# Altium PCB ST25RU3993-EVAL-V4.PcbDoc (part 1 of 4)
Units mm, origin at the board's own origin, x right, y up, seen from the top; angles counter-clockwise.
Board outline 76.25 x 96.25 mm, 6 copper layers (Top Layer, RF GND, Power, GND, Routing, Bottom GND), stack 1.022 mm thick; 319 components, 214 nets, 994 pads, 1429 vias.
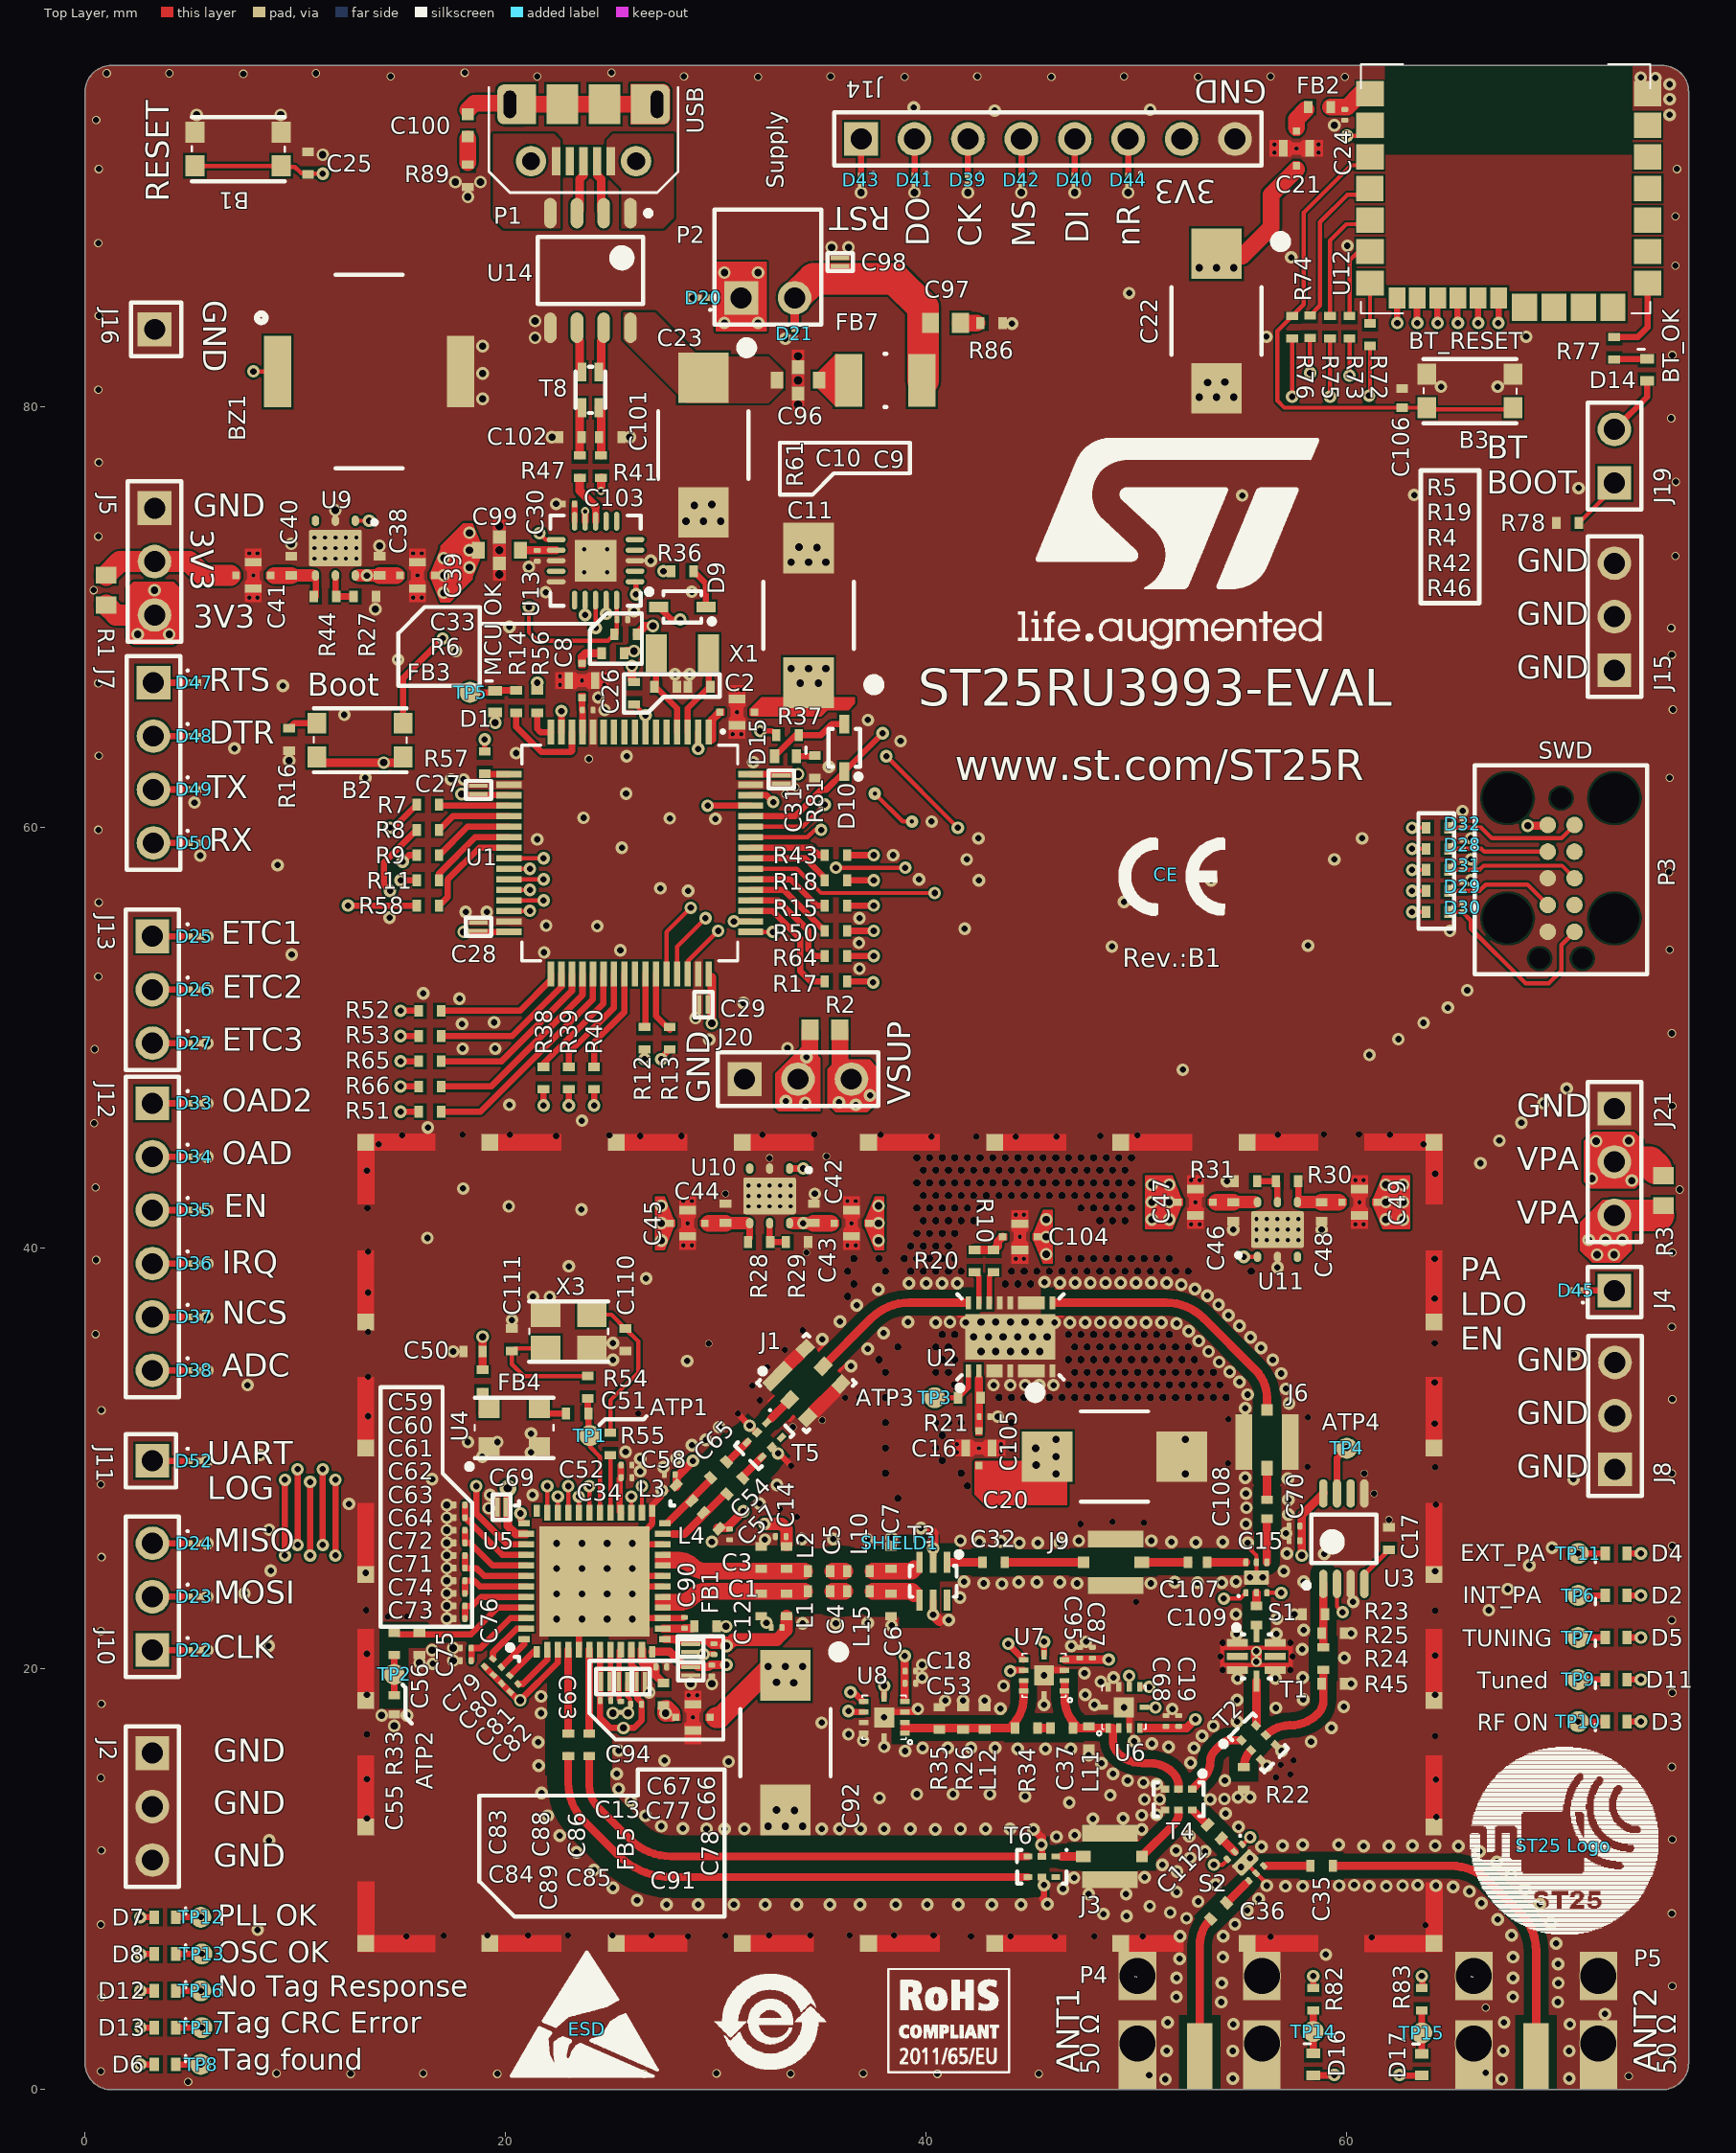
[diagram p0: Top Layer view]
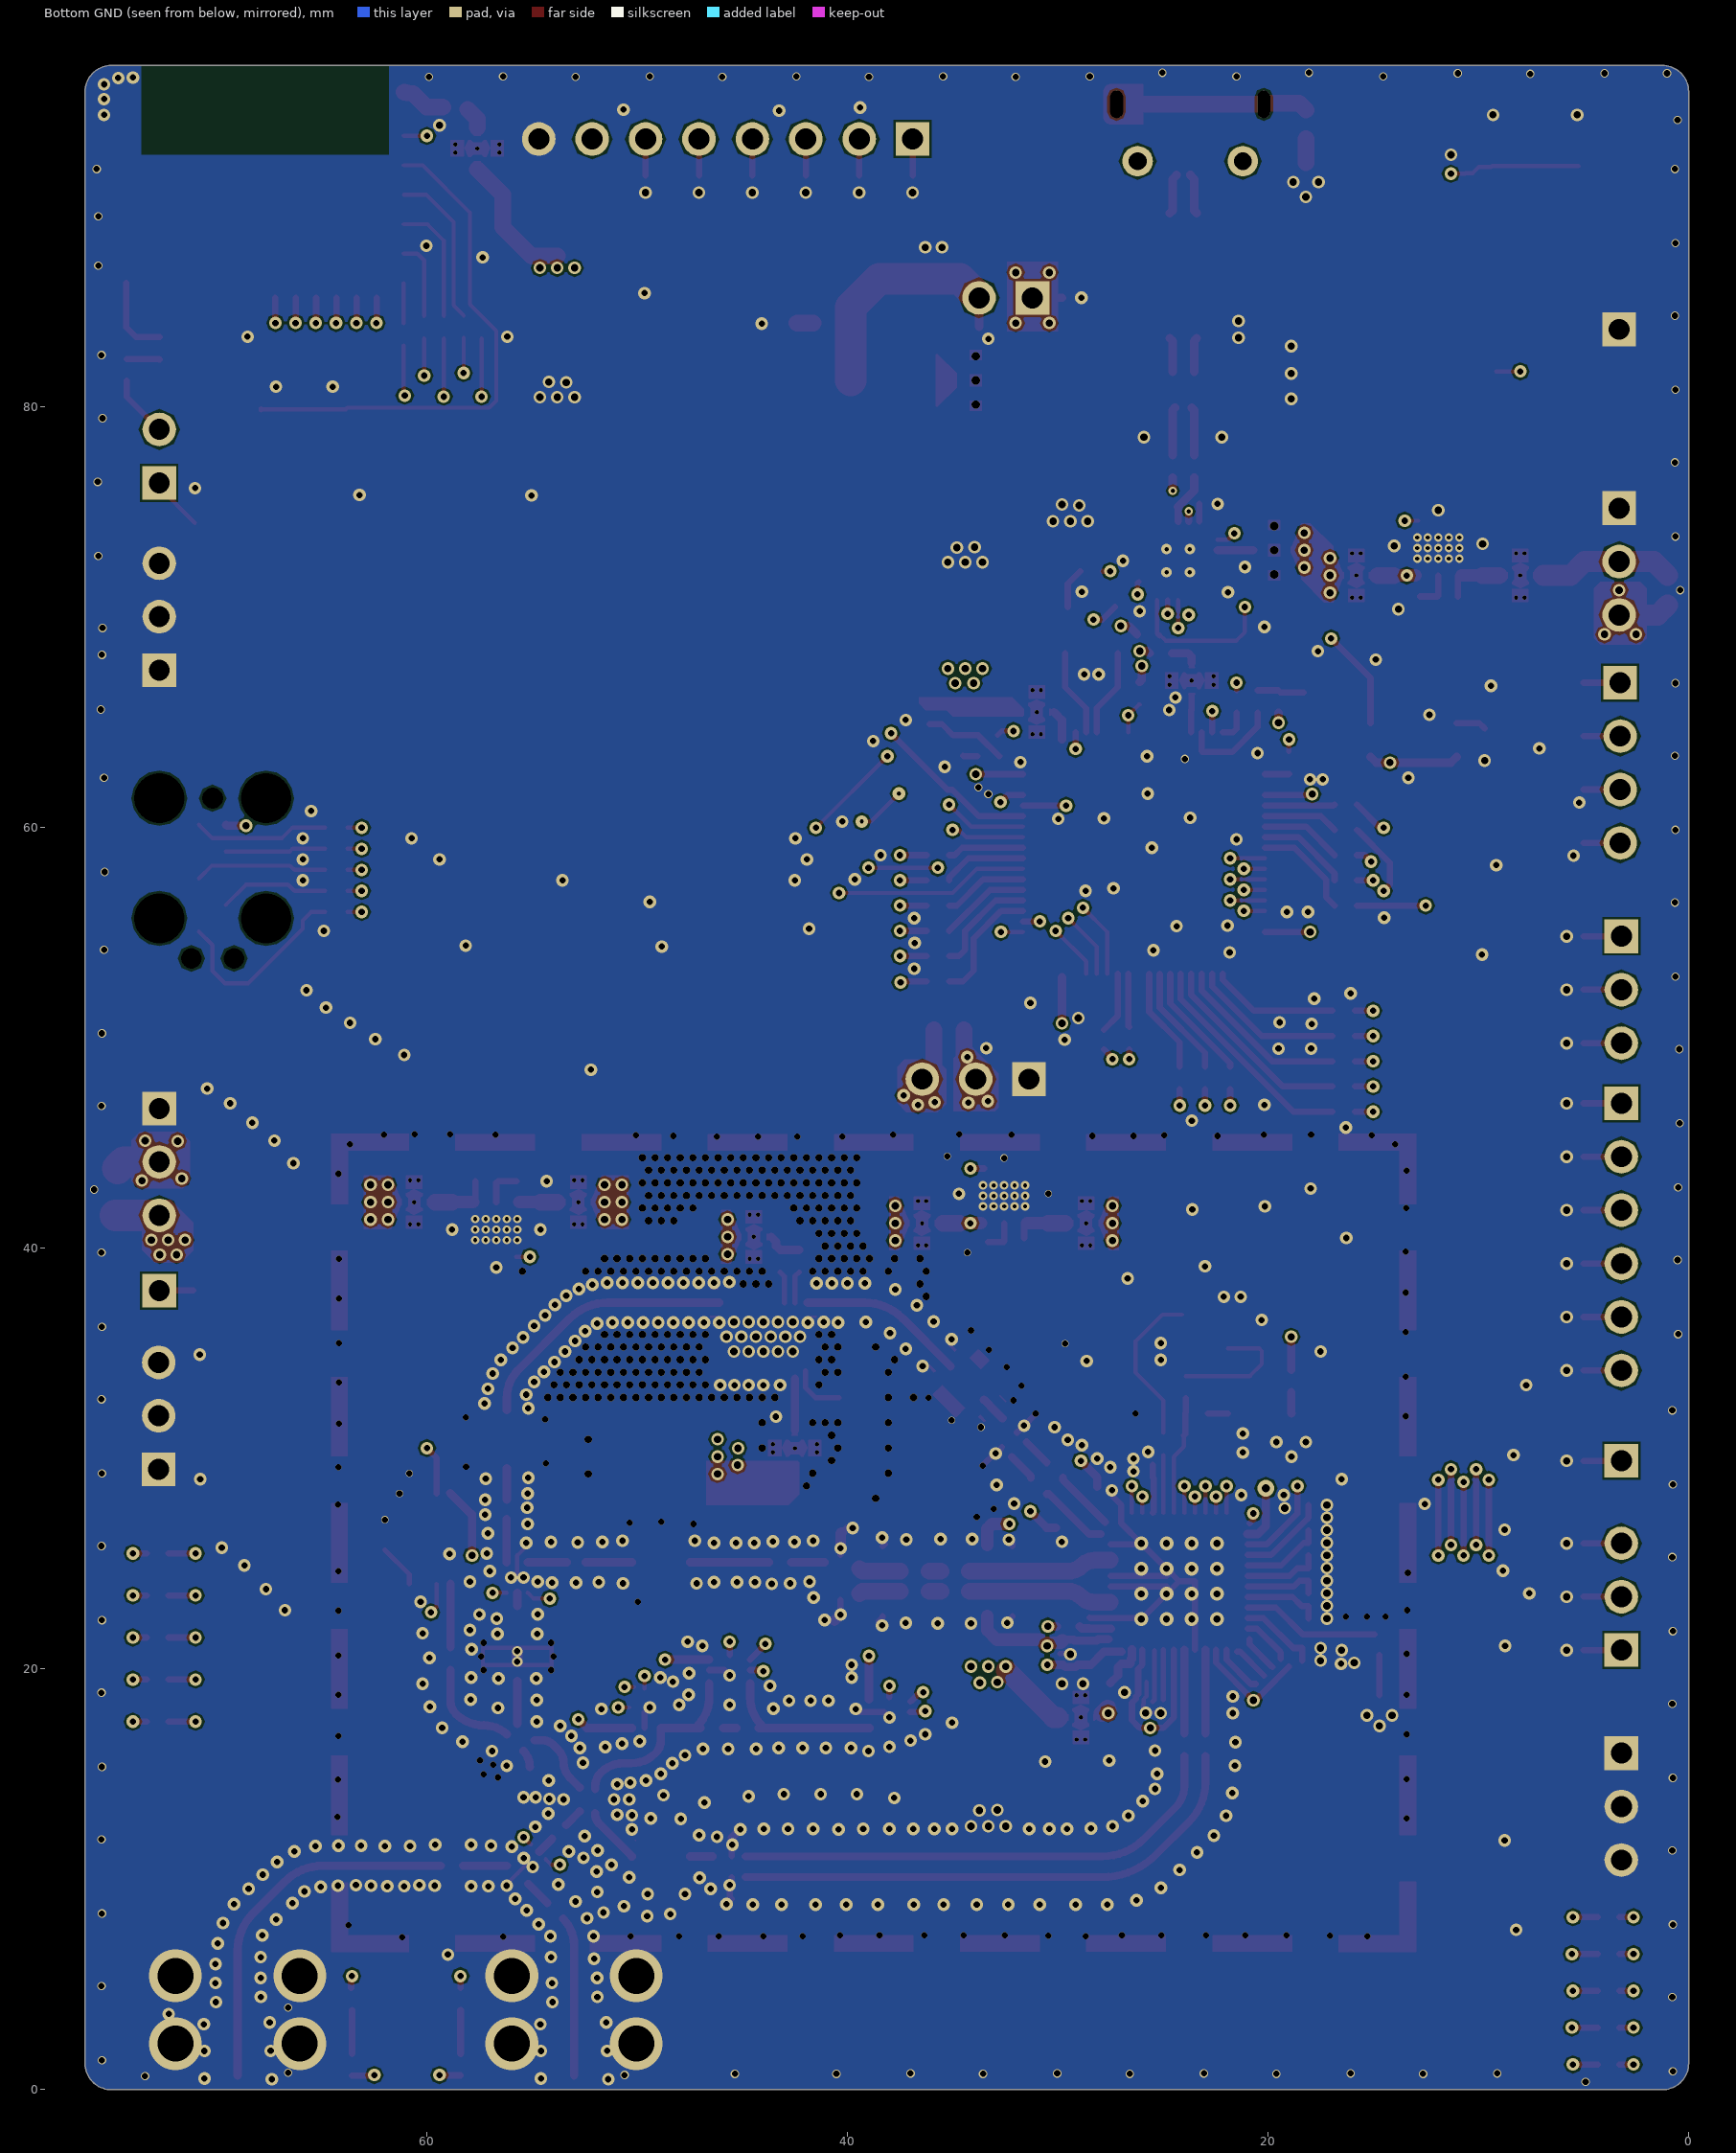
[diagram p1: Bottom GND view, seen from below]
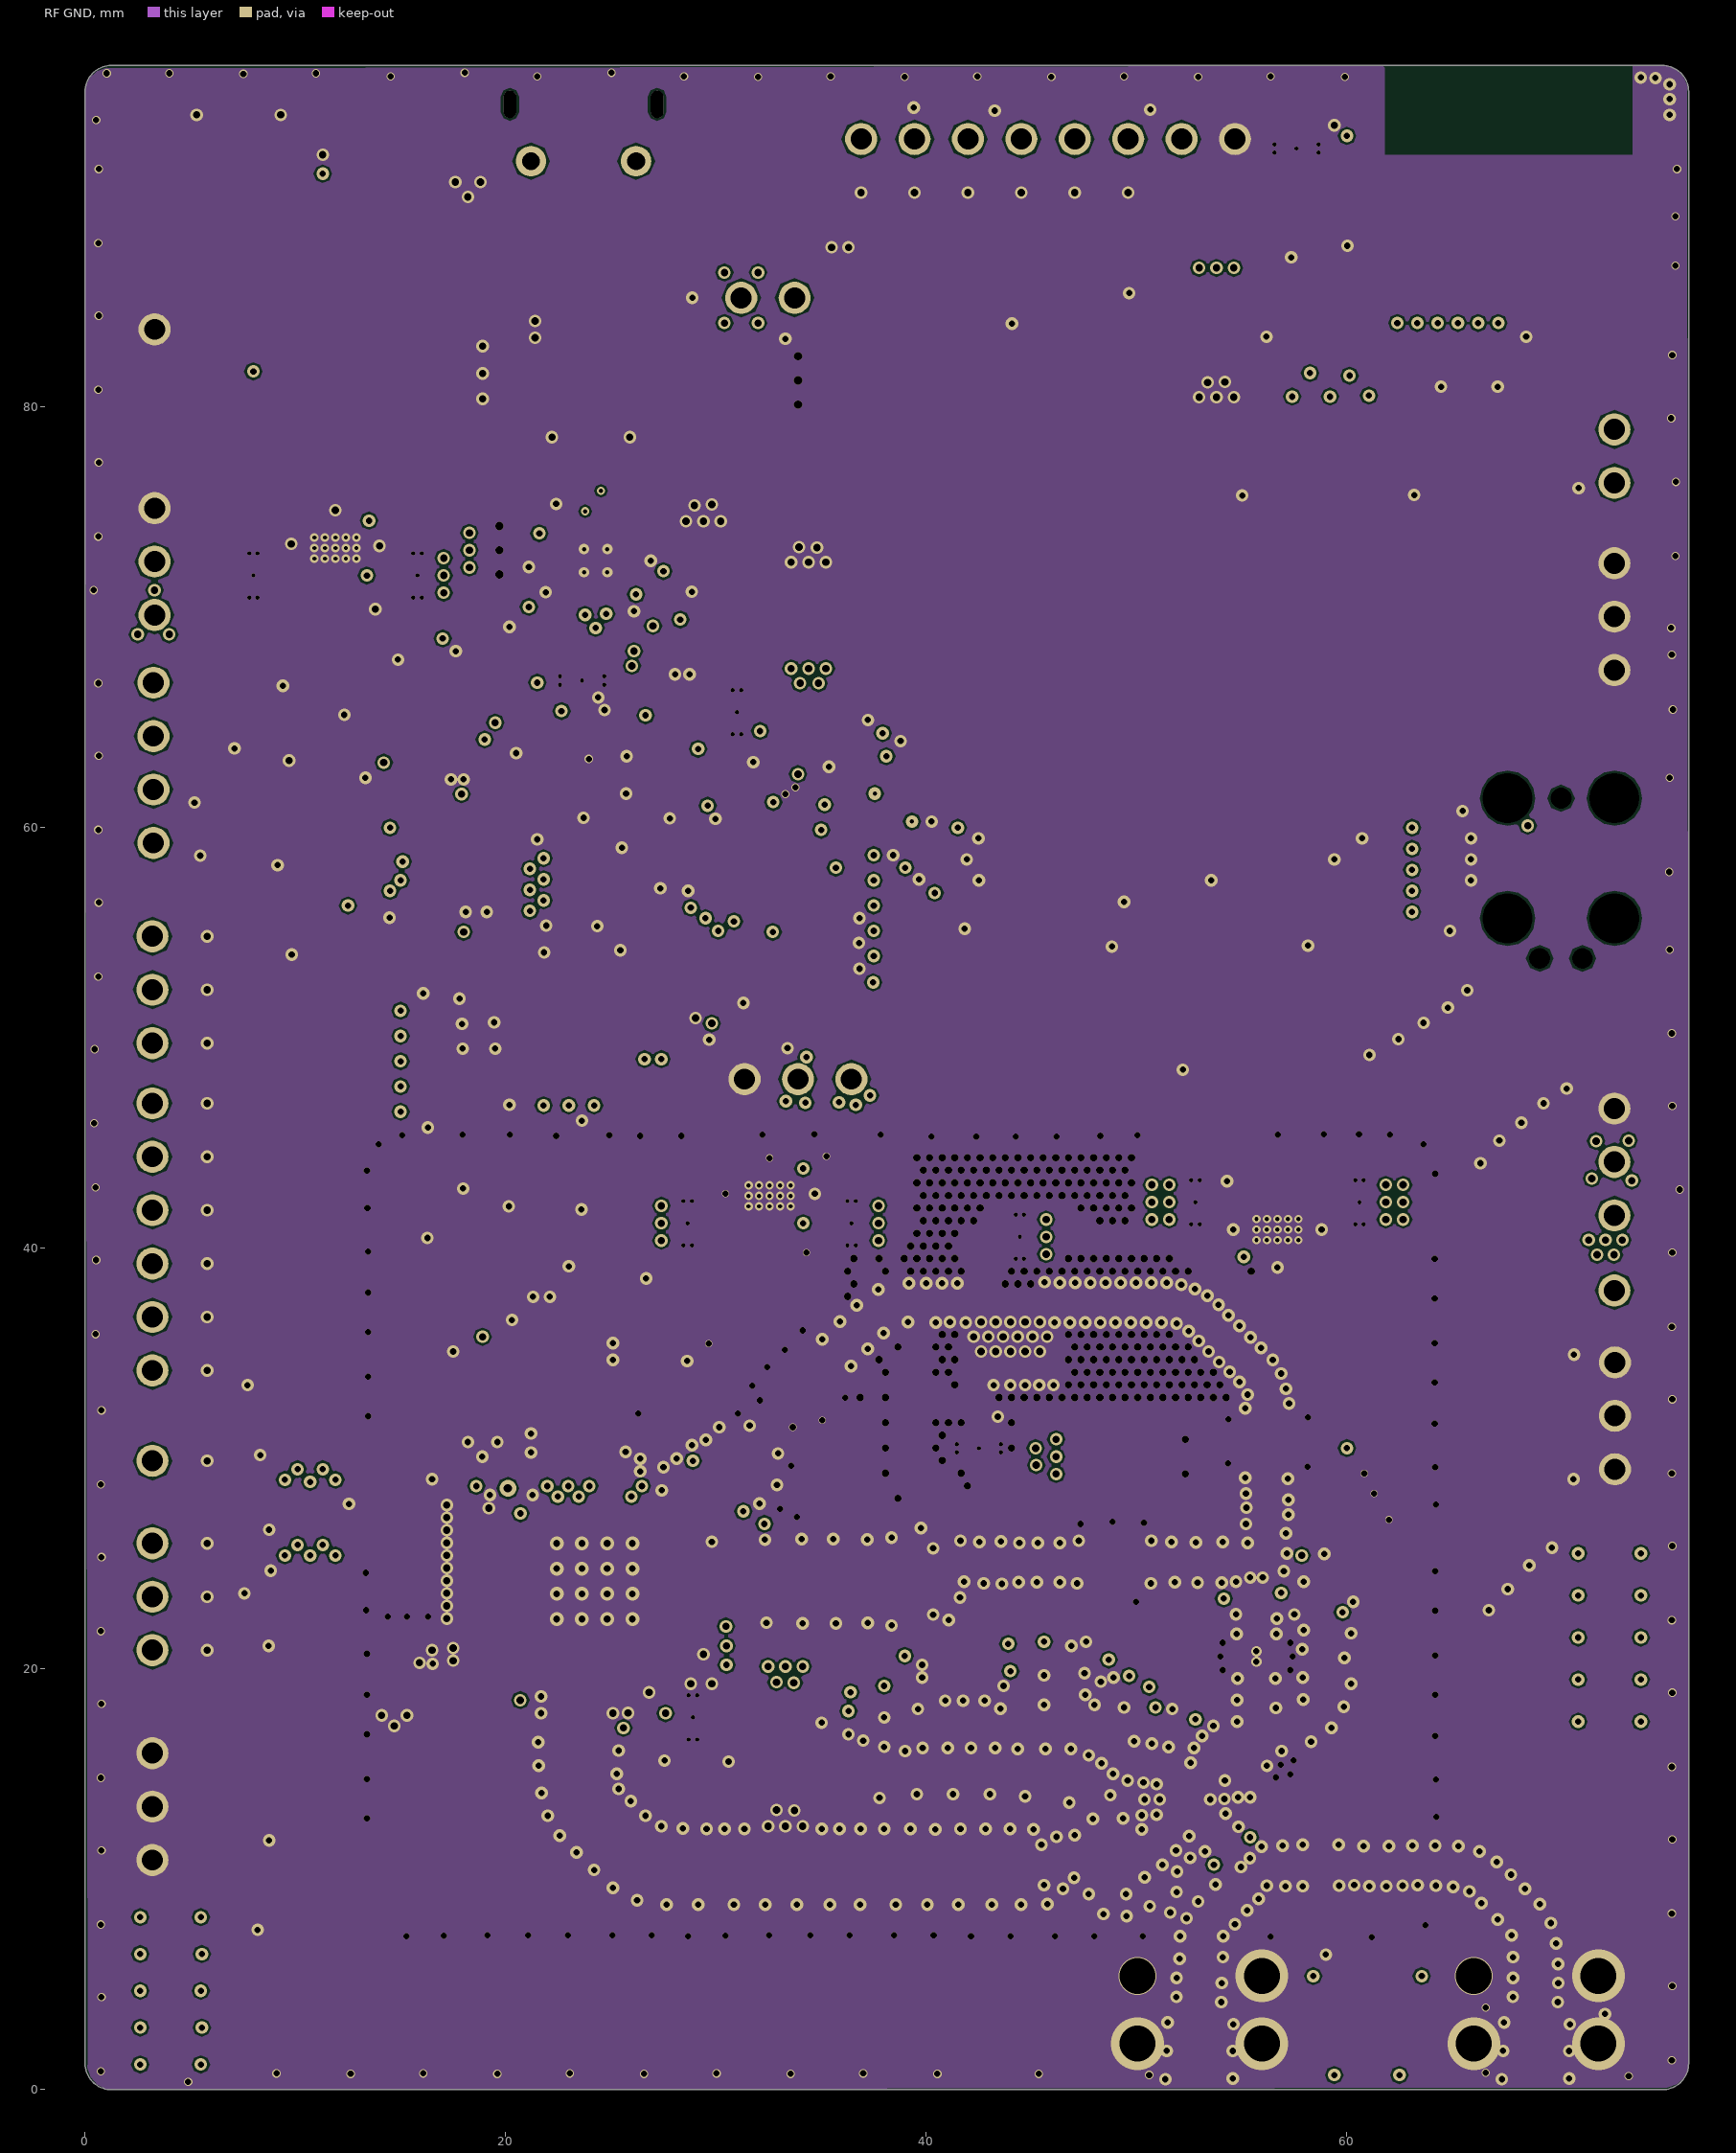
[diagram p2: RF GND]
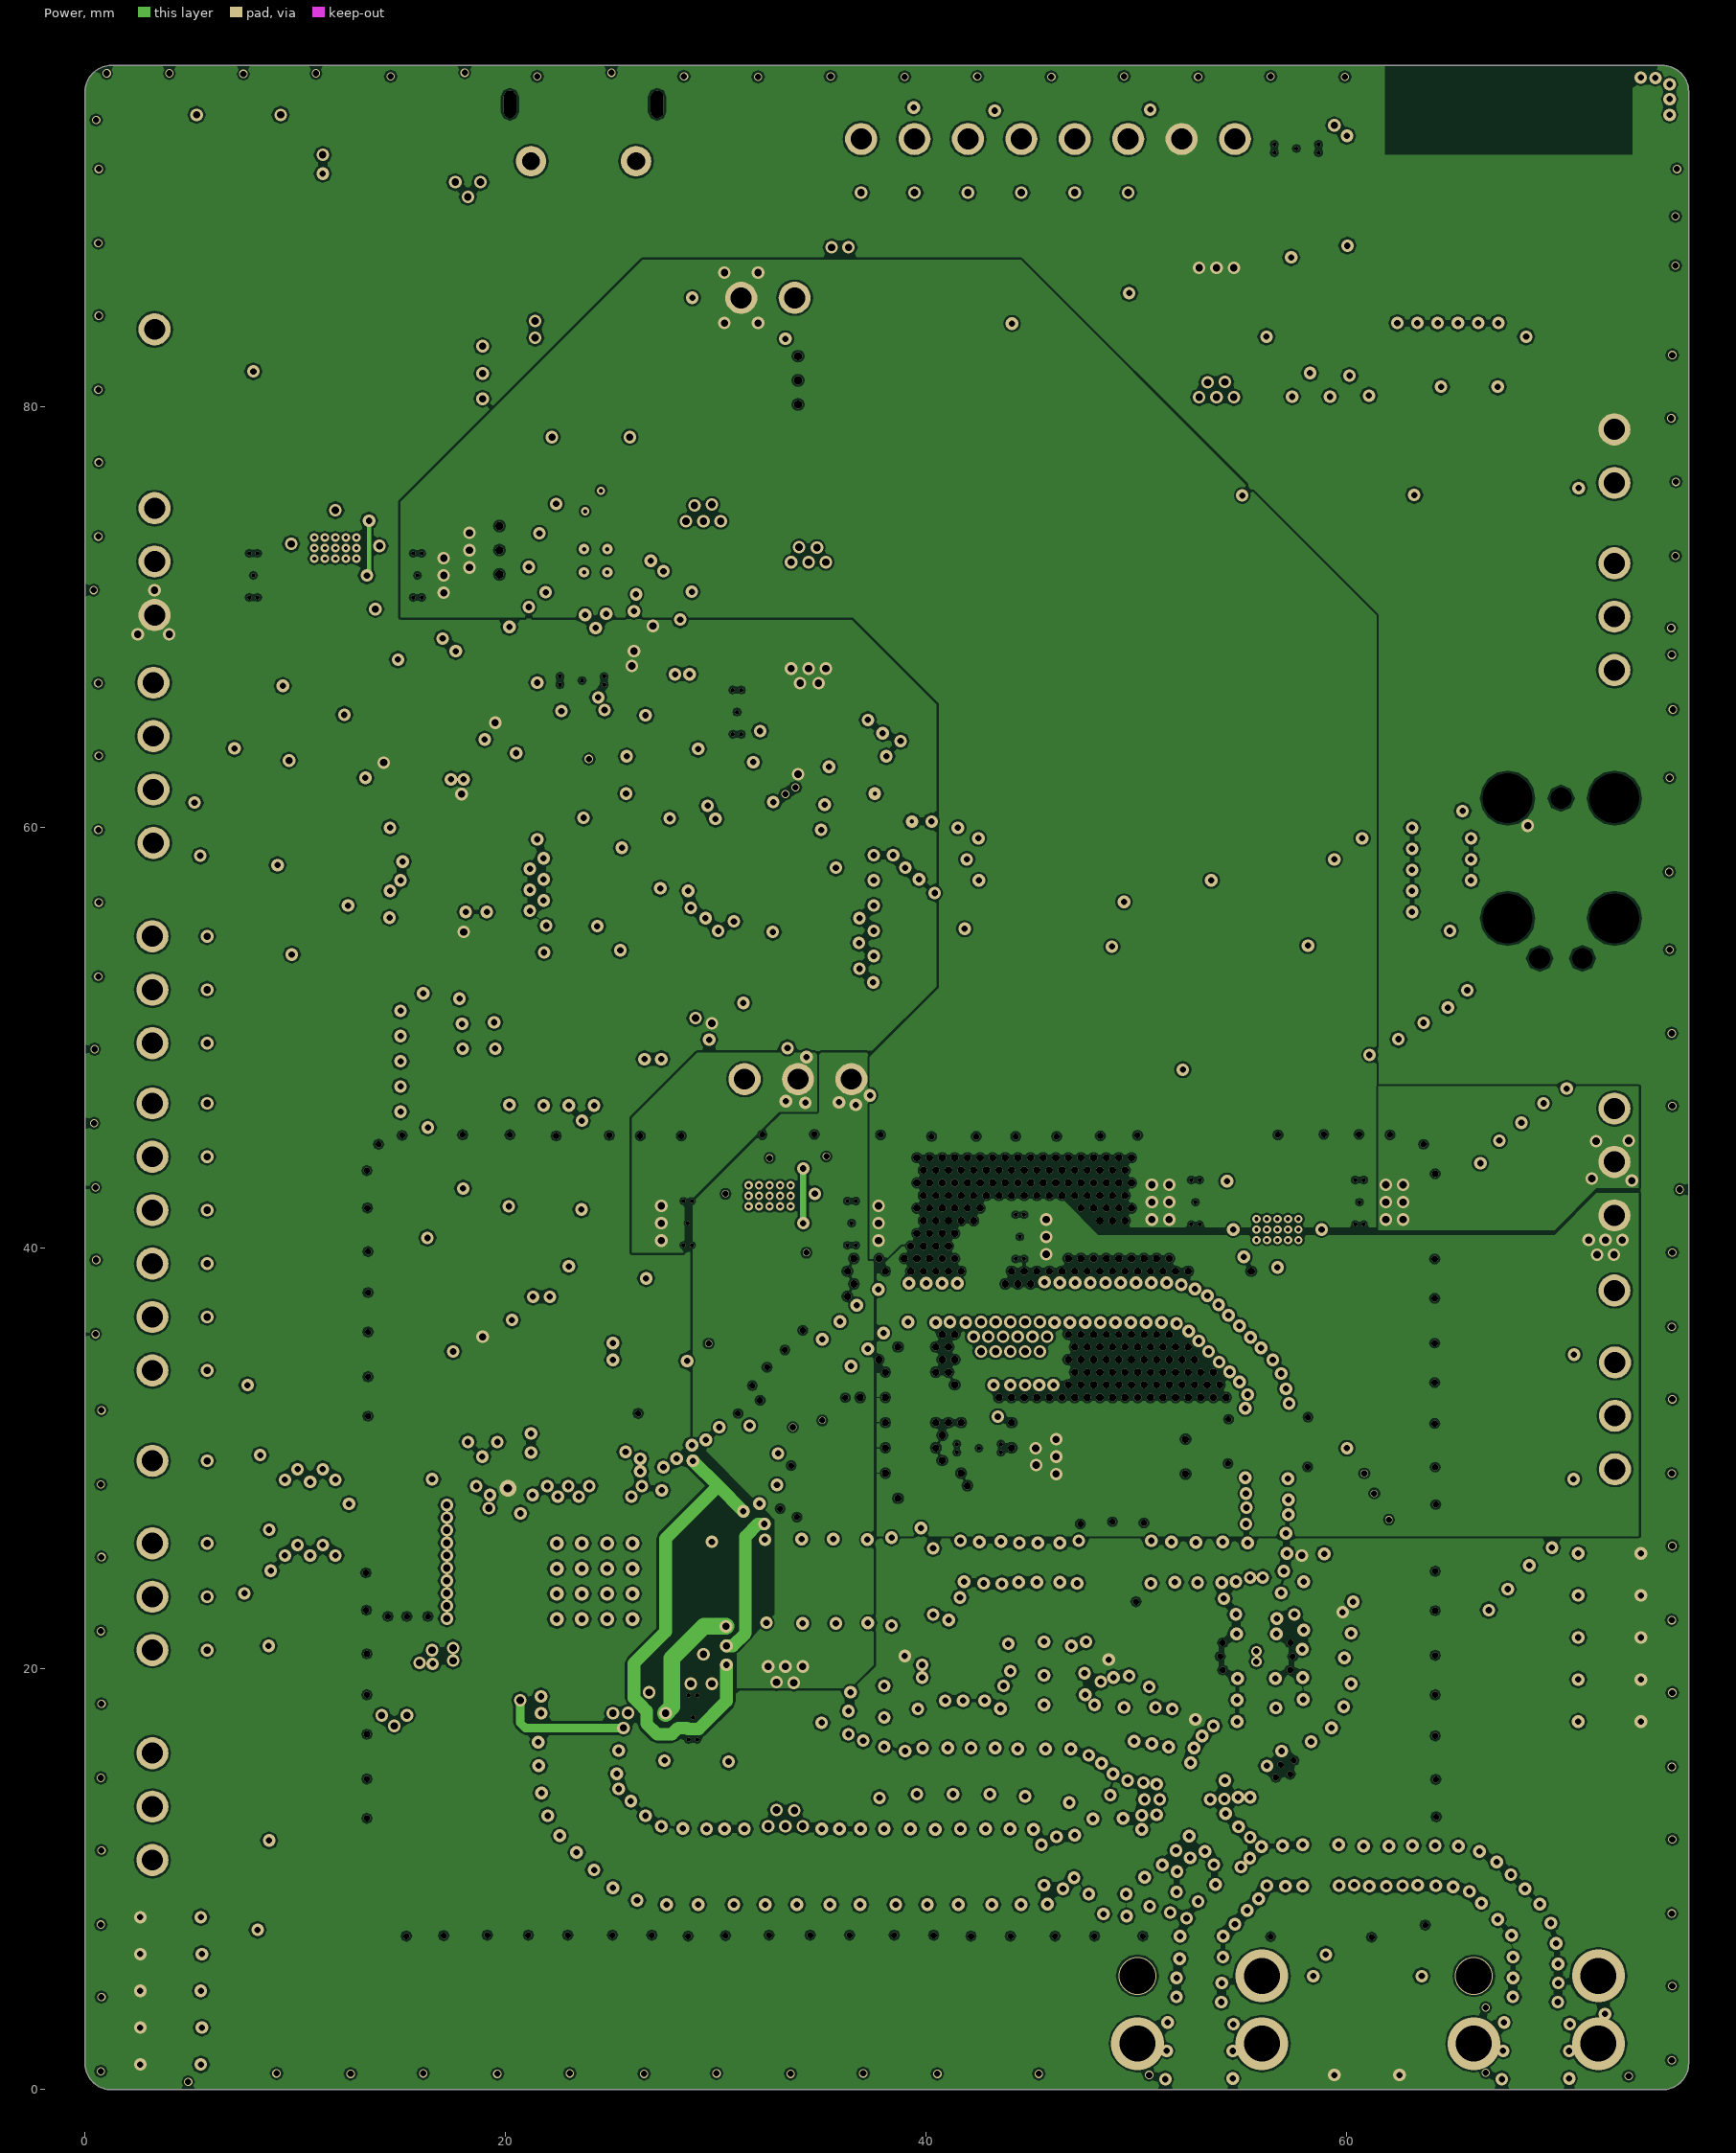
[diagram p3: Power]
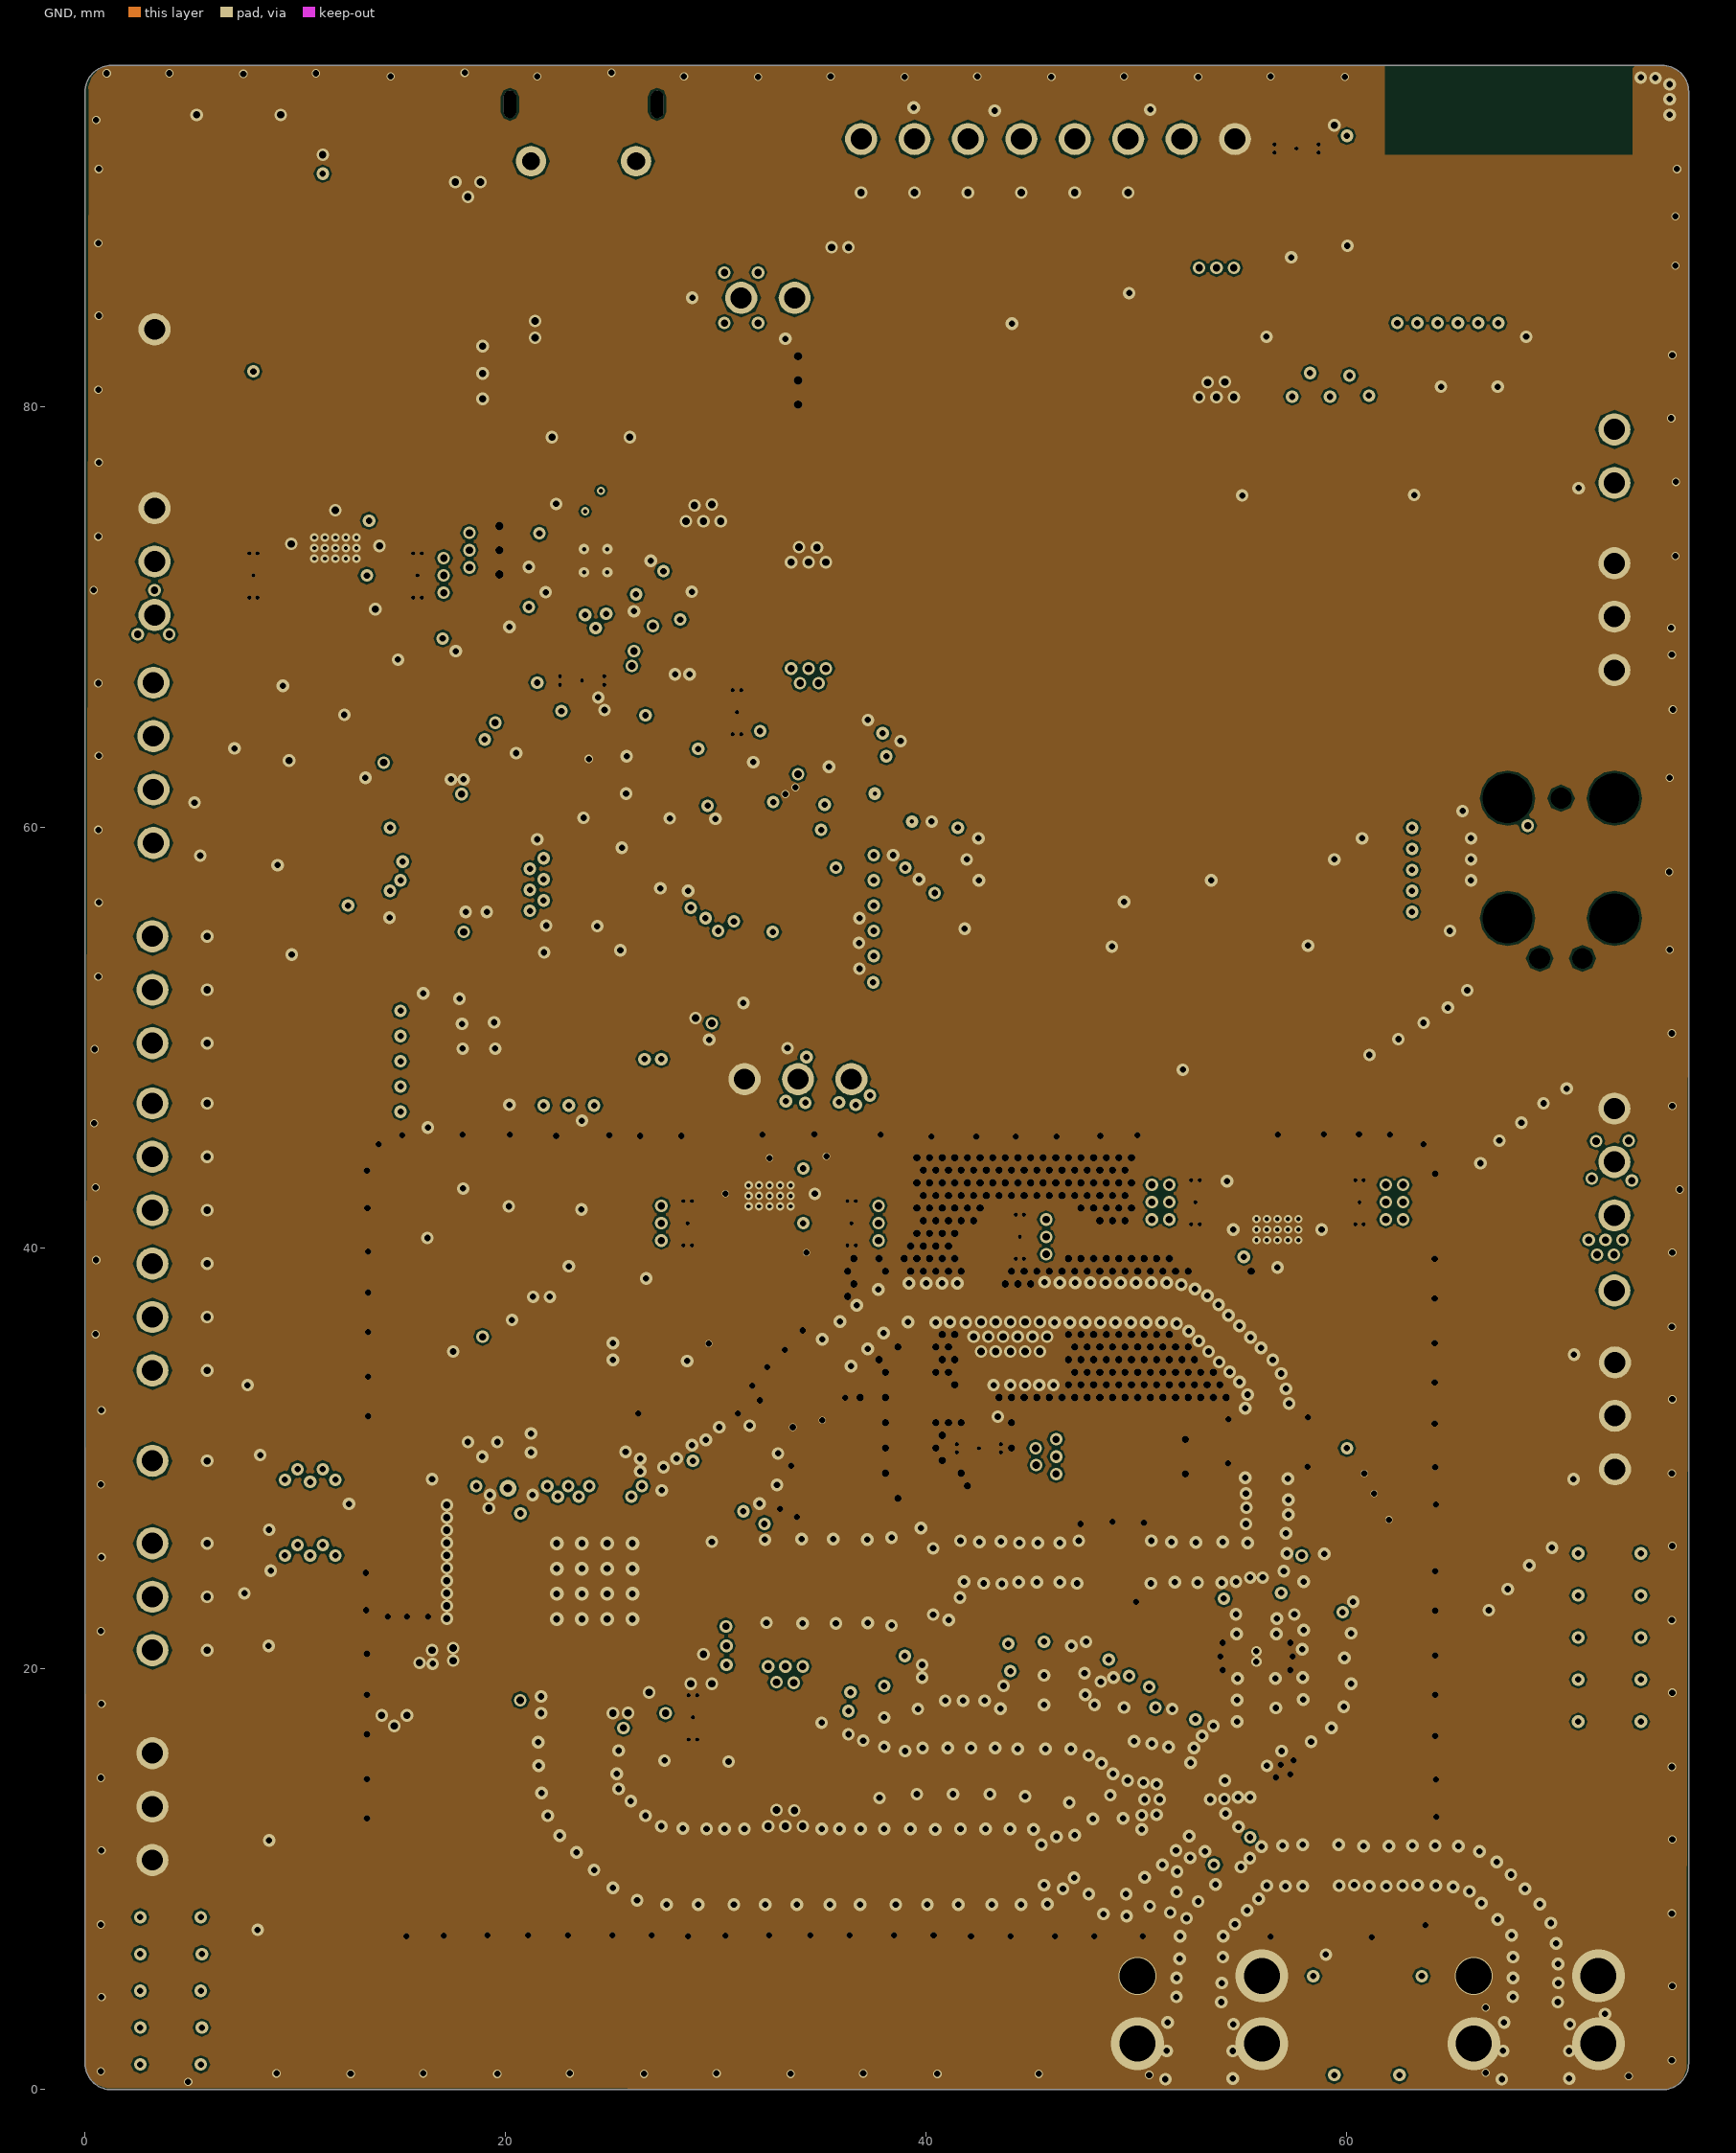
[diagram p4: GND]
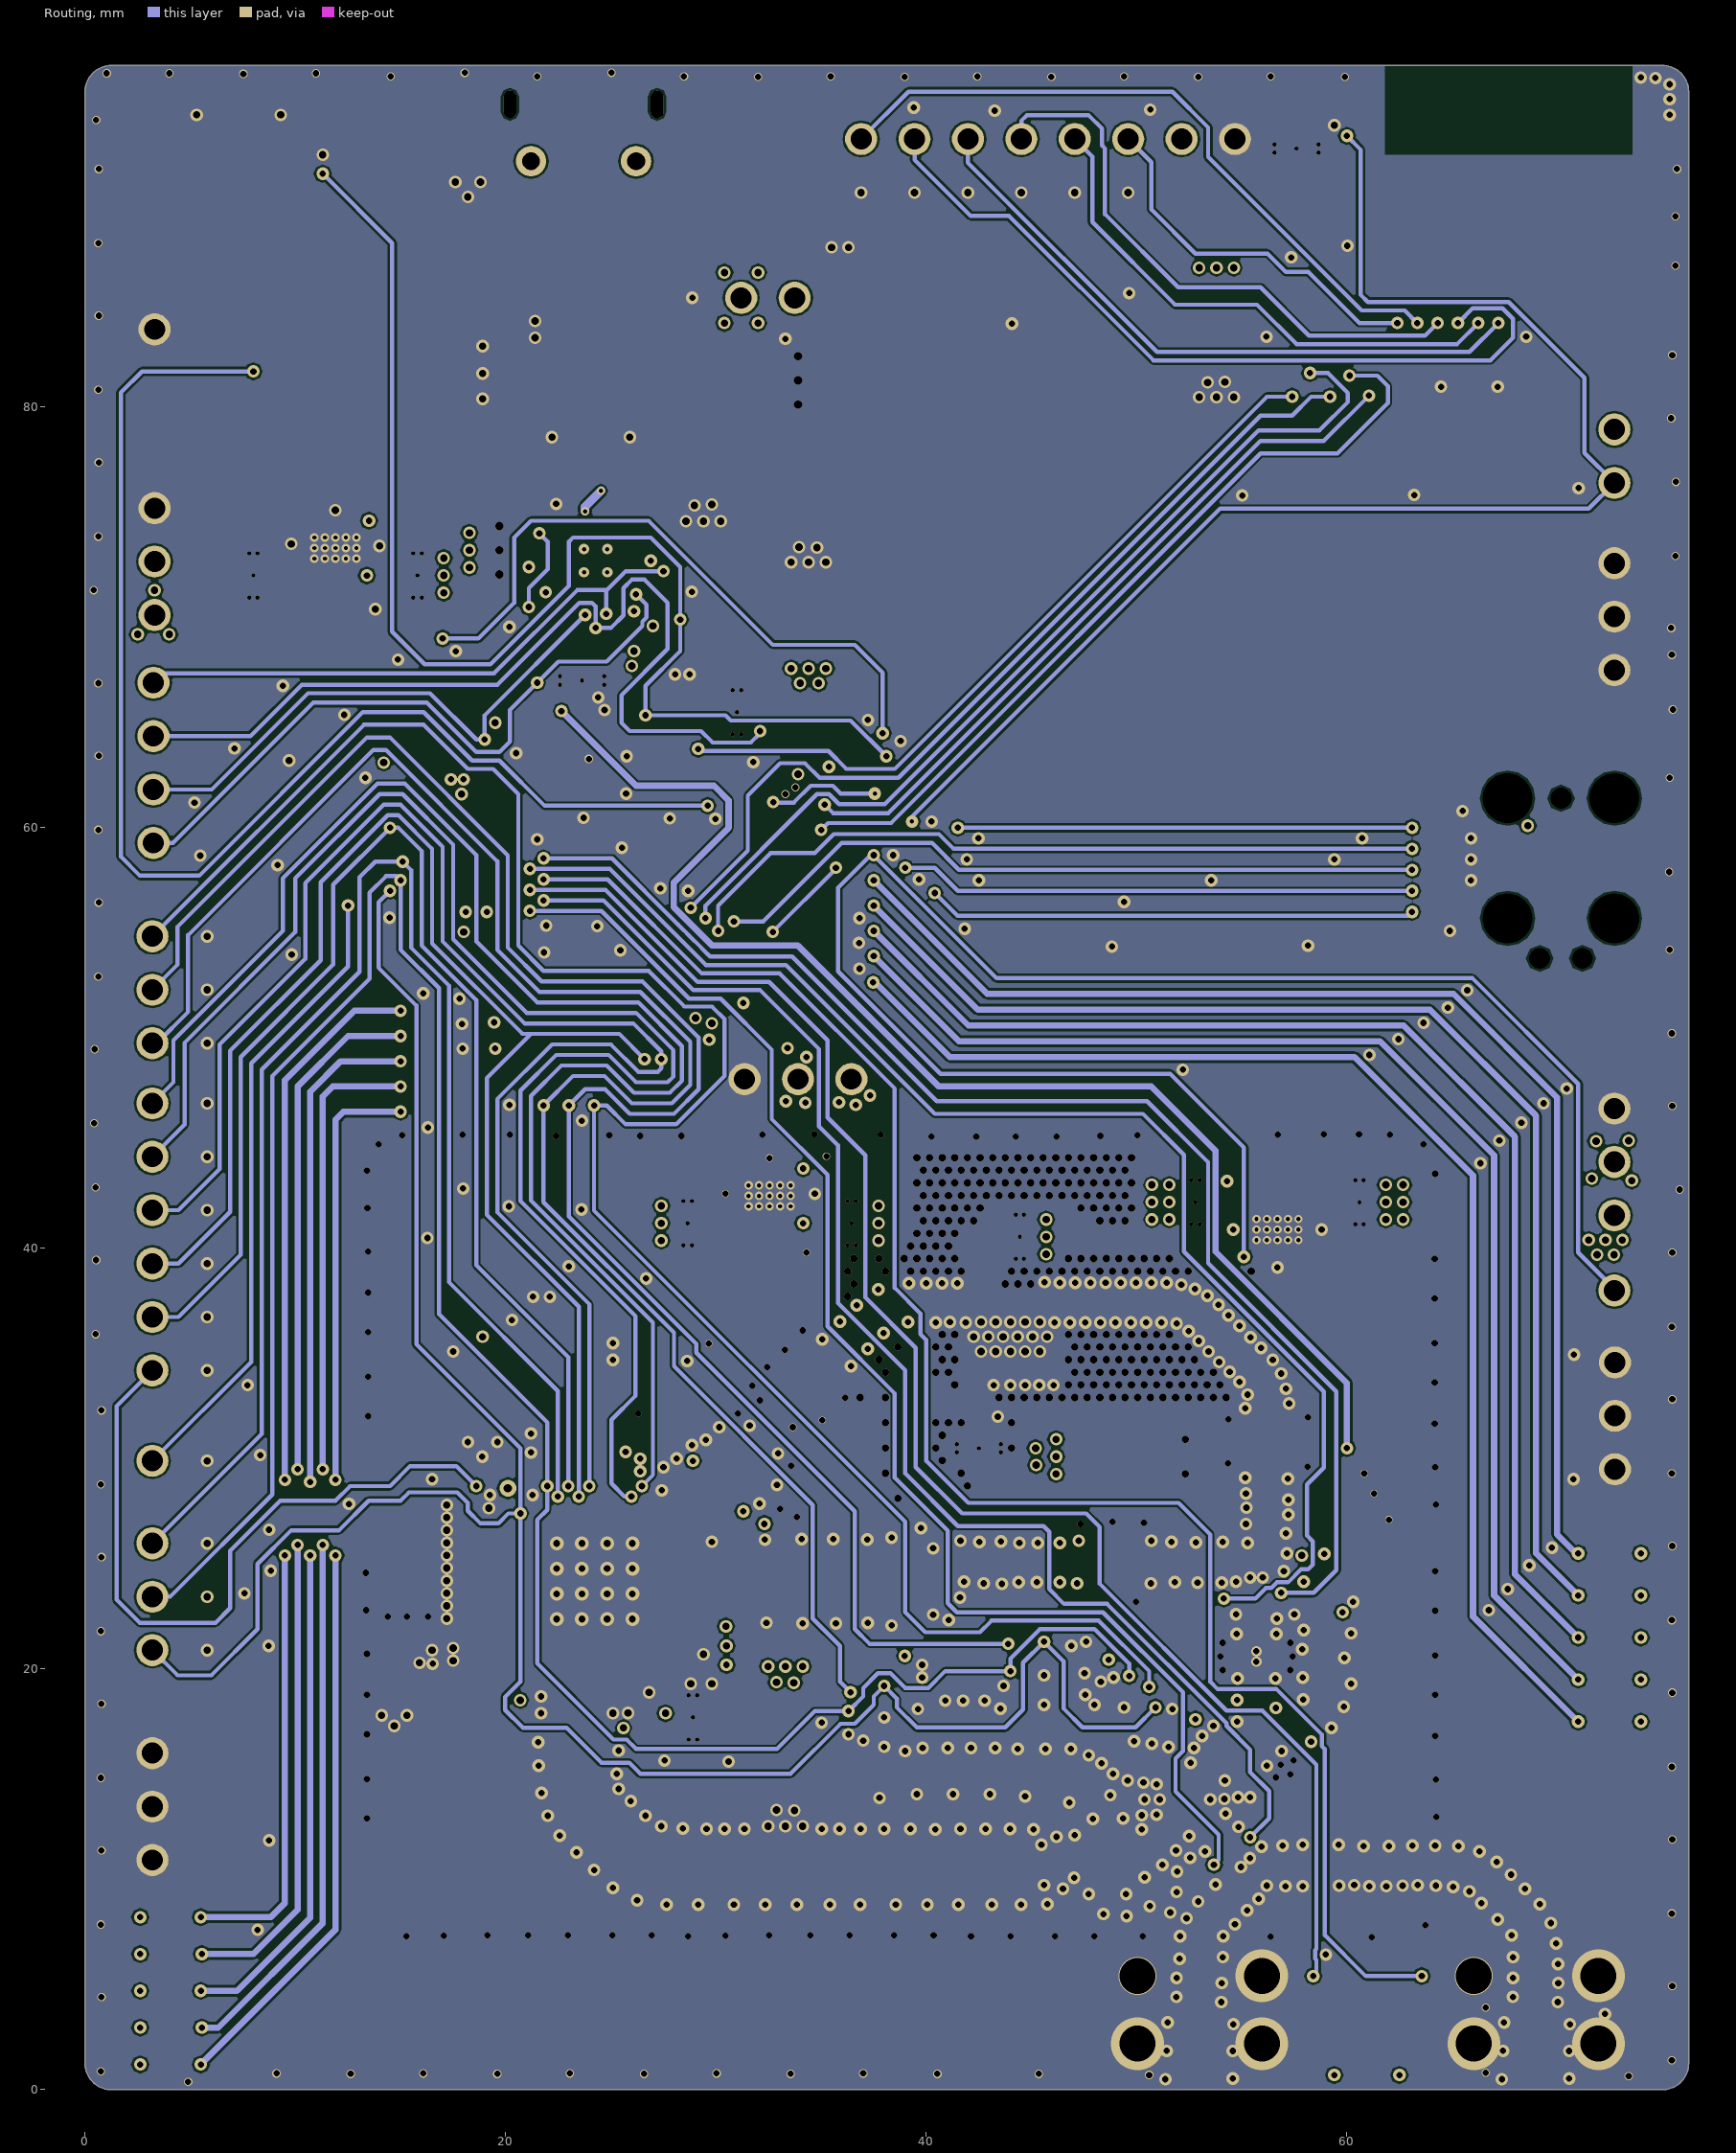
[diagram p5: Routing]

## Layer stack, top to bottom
Top Solder: solder mask 0.0102, Solder Resist, Dk 4.5
Top Layer: signal copper 0.043
Dielectric1: core 0.25, FR-4 (R-1755M), Dk 4.7
RF GND: signal copper 0.032
Dielectric2: prepreg 0.1, FR-4 (R-1755M), Dk 4.6
Power: signal copper 0.032
Dielectric3: core 0.1, FR-4 (R-1755M), Dk 4.6
GND: signal copper 0.036
Dielectric 5: prepreg 0.1, FR-4 (R-1755M), Dk 4.6
Routing: signal copper 0.036
Dielectric 4: core 0.25, FR-4 (R-1755M), Dk 4.7
Bottom GND: signal copper 0.043
Bottom Solder: solder mask 0.0102, Solder Resist, Dk 4.5

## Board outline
0,1.25 0,95 cw(c1.25,95) 1.25,96.25 75,96.25 cw(c75,95) 76.25,95 76.25,1.25 cw(c75,1.25) 75,0 1.25,0 cw(c1.25,1.25)

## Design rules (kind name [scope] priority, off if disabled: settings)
AssemblyTestPointUsage [All] p1 off:
AssemblyTestpoint [All] p1 off: testpointundercomponent=TRUE minsize=1.016 maxsize=2.54 preferedsize=1.524 minholesize=0 maxholesize=1.016 preferedholesize=0.813 testpointgrid=0.025 usegrid=TRUE gridtolerance=0 allowsidetop=TRUE allowsidebottom=TRUE
Clearance [InNetClass('Differential_RF') and IsTrack or InNetClass('Differential_RF') and IsArc or InNetClass('Differential_RF') and IsPad or InNet('PAOUT_N')or InNet('PAOUT_P')or InNet('NetC5_2') or InNet('NetC4_2') or InNet('NetC7_2')or InNet('NetC6_1') vs InNamedPolygon('Top GND')] p1: gap=0.8 ignorepadtopadclearanceinfootprint=FALSE except(0: Arc-Hole Track-Hole SMDPad-Hole THPad-Hole Via-Hole Fill-Hole Poly-Hole Region-Hole Text-Hole)
Clearance Clearance_3 [InNetClass('SE_CPWG') and IsTrack or InNetClass('SE_CPWG') and IsArc or InNetClass('SE_CPWG') and IsPad vs InNamedPolygon('Top GND')] p2: gap=0.4 ignorepadtopadclearanceinfootprint=FALSE except(0: Arc-Hole Track-Hole SMDPad-Hole THPad-Hole Via-Hole Fill-Hole Poly-Hole Region-Hole Text-Hole)
Clearance Clearance_1 [InNet('NetT4_1') vs InNet('CPL_TN')] p3: gap=0.1 ignorepadtopadclearanceinfootprint=FALSE except(0: Arc-Hole Track-Hole SMDPad-Hole THPad-Hole Via-Hole Fill-Hole Poly-Hole Region-Hole Text-Hole)
Clearance Clearance_4 [InComponent('T4') or InComponent('U2') or InComponent('U3')] p4: gap=0.1 ignorepadtopadclearanceinfootprint=FALSE except(0: Arc-Hole Track-Hole SMDPad-Hole THPad-Hole Via-Hole Fill-Hole Poly-Hole Region-Hole Text-Hole)
Clearance Clearance_2 [All] p5: gap=0.1 ignorepadtopadclearanceinfootprint=FALSE except(0: Arc-Hole Track-Hole SMDPad-Hole THPad-Hole Via-Hole Fill-Hole Poly-Hole Region-Hole Text-Hole)
ComponentClearance ComponentClearance_2 [InComponent('SHIELD1')] p1: gap=0 collisioncheckmode=3 verticalgap=0 showdistances=FALSE
ComponentClearance [All] p2: gap=0.254 collisioncheckmode=3 verticalgap=0.254 showdistances=FALSE
DiffPairsRouting DiffPairsRouting_3 [InDifferentialPair('IN')] p1: maxlimit=0.58 minlimit=0.56 mostfreqgap=0.57 toplayer_minwidth=0.34 toplayer_maxwidth=0.38 toplayer_prefwidth=0.37 midlayer1_minwidth=0.34 midlayer1_maxwidth=0.38 midlayer1_prefwidth=0.37 midlayer2_minwidth=0.34 midlayer2_maxwidth=0.38 midlayer2_prefwidth=0.37 midlayer3_minwidth=0.34 midlayer3_maxwidth=0.38 midlayer3_prefwidth=0.37 midlayer4_minwidth=0.34 midlayer4_maxwidth=0.38 midlayer4_prefwidth=0.37 bottomlayer_minwidth=0.34 bottomlayer_maxwidth=0.38 bottomlayer_prefwidth=0.37 maxuncoupledlength=0
DiffPairsRouting DiffPairsRouting_6 [InDifferentialPair('RX')] p2: maxlimit=0.58 minlimit=0.56 mostfreqgap=0.57 toplayer_minwidth=0.37 toplayer_maxwidth=0.38 toplayer_prefwidth=0.37 midlayer1_minwidth=0.37 midlayer1_maxwidth=0.38 midlayer1_prefwidth=0.37 midlayer2_minwidth=0.37 midlayer2_maxwidth=0.38 midlayer2_prefwidth=0.37 midlayer3_minwidth=0.37 midlayer3_maxwidth=0.38 midlayer3_prefwidth=0.37 midlayer4_minwidth=0.37 midlayer4_maxwidth=0.38 midlayer4_prefwidth=0.37 bottomlayer_minwidth=0.37 bottomlayer_maxwidth=0.38 bottomlayer_prefwidth=0.37 maxuncoupledlength=0
DiffPairsRouting DiffPairsRouting_2 [InDifferentialPair('TX')] p3: maxlimit=0.58 minlimit=0.56 mostfreqgap=0.57 toplayer_minwidth=0.37 toplayer_maxwidth=0.38 toplayer_prefwidth=0.37 midlayer1_minwidth=0.37 midlayer1_maxwidth=0.38 midlayer1_prefwidth=0.37 midlayer2_minwidth=0.37 midlayer2_maxwidth=0.38 midlayer2_prefwidth=0.37 midlayer3_minwidth=0.37 midlayer3_maxwidth=0.38 midlayer3_prefwidth=0.37 midlayer4_minwidth=0.37 midlayer4_maxwidth=0.38 midlayer4_prefwidth=0.37 bottomlayer_minwidth=0.37 bottomlayer_maxwidth=0.38 bottomlayer_prefwidth=0.37 maxuncoupledlength=5
DiffPairsRouting DiffPairsRouting_5 [InDifferentialPair('RFO')] p4: maxlimit=0.58 minlimit=0.56 mostfreqgap=0.57 toplayer_minwidth=0.37 toplayer_maxwidth=0.38 toplayer_prefwidth=0.37 midlayer1_minwidth=0.37 midlayer1_maxwidth=0.38 midlayer1_prefwidth=0.37 midlayer2_minwidth=0.37 midlayer2_maxwidth=0.38 midlayer2_prefwidth=0.37 midlayer3_minwidth=0.37 midlayer3_maxwidth=0.38 midlayer3_prefwidth=0.37 midlayer4_minwidth=0.37 midlayer4_maxwidth=0.38 midlayer4_prefwidth=0.37 bottomlayer_minwidth=0.37 bottomlayer_maxwidth=0.38 bottomlayer_prefwidth=0.37 maxuncoupledlength=5
DiffPairsRouting DiffPairsRouting_1 [InDifferentialPair('D_CON')] p5: maxlimit=0.61 minlimit=0.1 mostfreqgap=0.6 toplayer_minwidth=0.2 toplayer_maxwidth=0.43 toplayer_prefwidth=0.42 midlayer1_minwidth=0.2 midlayer1_maxwidth=0.43 midlayer1_prefwidth=0.42 midlayer2_minwidth=0.2 midlayer2_maxwidth=0.43 midlayer2_prefwidth=0.42 midlayer3_minwidth=0.2 midlayer3_maxwidth=0.43 midlayer3_prefwidth=0.42 midlayer4_minwidth=0.2 midlayer4_maxwidth=0.43 midlayer4_prefwidth=0.42 bottomlayer_minwidth=0.2 bottomlayer_maxwidth=0.43 bottomlayer_prefwidth=0.42 maxuncoupledlength=5
DiffPairsRouting [InDifferentialPair('D_ESD')] p6: maxlimit=0.61 minlimit=0.3 mostfreqgap=0.6 toplayer_minwidth=0.41 toplayer_maxwidth=0.43 toplayer_prefwidth=0.42 midlayer1_minwidth=0.41 midlayer1_maxwidth=0.43 midlayer1_prefwidth=0.42 midlayer2_minwidth=0.41 midlayer2_maxwidth=0.43 midlayer2_prefwidth=0.42 midlayer3_minwidth=0.41 midlayer3_maxwidth=0.43 midlayer3_prefwidth=0.42 midlayer4_minwidth=0.41 midlayer4_maxwidth=0.43 midlayer4_prefwidth=0.42 bottomlayer_minwidth=0.41 bottomlayer_maxwidth=0.43 bottomlayer_prefwidth=0.42 maxuncoupledlength=5
DiffPairsRouting DiffPairsRouting_7 [InDifferentialPair('D_CMC')] p7: maxlimit=0.61 minlimit=0.3 mostfreqgap=0.6 toplayer_minwidth=0.41 toplayer_maxwidth=0.43 toplayer_prefwidth=0.42 midlayer1_minwidth=0.41 midlayer1_maxwidth=0.43 midlayer1_prefwidth=0.42 midlayer2_minwidth=0.41 midlayer2_maxwidth=0.43 midlayer2_prefwidth=0.42 midlayer3_minwidth=0.41 midlayer3_maxwidth=0.43 midlayer3_prefwidth=0.42 midlayer4_minwidth=0.41 midlayer4_maxwidth=0.43 midlayer4_prefwidth=0.42 bottomlayer_minwidth=0.41 bottomlayer_maxwidth=0.43 bottomlayer_prefwidth=0.42 maxuncoupledlength=5
DiffPairsRouting DiffPairsRouting_8 [InDifferentialPair('D_UART')] p8: maxlimit=0.61 minlimit=0.3 mostfreqgap=0.6 toplayer_minwidth=0.41 toplayer_maxwidth=0.43 toplayer_prefwidth=0.42 midlayer1_minwidth=0.41 midlayer1_maxwidth=0.43 midlayer1_prefwidth=0.42 midlayer2_minwidth=0.41 midlayer2_maxwidth=0.43 midlayer2_prefwidth=0.42 midlayer3_minwidth=0.41 midlayer3_maxwidth=0.43 midlayer3_prefwidth=0.42 midlayer4_minwidth=0.41 midlayer4_maxwidth=0.43 midlayer4_prefwidth=0.42 bottomlayer_minwidth=0.41 bottomlayer_maxwidth=0.43 bottomlayer_prefwidth=0.42 maxuncoupledlength=5
FabricationTestPointUsage [All] p1 off: valid=0 allowmultiple=FALSE
FabricationTestpoint [All] p1 off: side=3 testpointundercomponent=TRUE minsize=1.016 maxsize=2.54 preferedsize=1.524 minholesize=0 maxholesize=1.016 preferedholesize=0.813 testpointgrid=0.025 allowsidetop=TRUE allowsidebottom=TRUE usegrid=TRUE gridtolerance=0
HoleSize FabricationTestpoint_1 [All] p1 off: absolutevalues=TRUE maxlimit=2.54 minlimit=0.025 maxpercent=80.000 minpercent=20.000
HoleSize FabricationTestPointUsage_1 [All] p2 off: absolutevalues=TRUE maxlimit=2.54 minlimit=0.025 maxpercent=80.000 minpercent=20.000
HoleSize [All] p3: absolutevalues=TRUE maxlimit=10 minlimit=0.15 maxpercent=80.000 minpercent=20.000
HoleToHoleClearance [ViaDiameter = 0.3] p1: gap=0.1 allowstackedmicrovias=TRUE
HoleToHoleClearance HoleToHoleClearance_1 [All] p2: gap=0.2 allowstackedmicrovias=TRUE
MatchedLengths [InNet('NetP1_2') or InNet('NetP2_2')] p1: tolerance=10 checknetsindiffpair=FALSE checkdiffpairvsdiffpair=TRUE checkxsignals=TRUE checkothers=TRUE
MinimumSolderMaskSliver [All] p1: minsoldermaskwidth=0.07
PlaneClearance [All] p1: clearance=0.5
PlaneConnect [All] p1: planeconnectstyle=Direct reliefexpansion=0.4 reliefentries=4 reliefconductorwidth=0.15 reliefairgap=0.15
PolygonConnect PolygonConnect_1 [InNet('GND')or InNet('MOD_BPLUS')or InNet('VPA')or InNet('VSUP')or InNet('5V') or InNet('NetC45_3') or InNet('NetC49_3')or InNet('VBUS')or InNet('NetP1_1') or InNet('NetC23_1')  or InNet('3V3')  or InNet('NetP1_5')] p1: connectstyle=Direct reliefconductorwidth=0.254 reliefentries=4 polygonreliefangle="90 Angle" airgapwidth=0.254
PolygonConnect [All] p2: connectstyle=Relief reliefconductorwidth=0.15 reliefentries=4 polygonreliefangle="90 Angle" airgapwidth=0.254
RoutingCorners [All] p1: cornerstyle=45-Degree minsetback=1.25 maxsetback=1.25
RoutingVias [All] p1: holewidth=0.2 width=0.6 viastyle="Through Hole" minholewidth=0.2 minwidth=0.2 maxholewidth=10 maxwidth=20
ShortCircuit ShortCircuit_2 [InNamedPolygon('Bottom GND') or InNamedPolygon('GND Poly') vs IsRegion and OnMultiLayer] p1: allowed=TRUE
ShortCircuit ShortCircuit_3 [ViaDiameter = 1] p2: allowed=TRUE
ShortCircuit ShortCircuit_1 [InComponent('B1')] p3: allowed=TRUE
ShortCircuit [All] p4: allowed=FALSE
SilkToSilkClearance [All] p1: silktosilkclearance=0.15
SilkToSolderMaskClearance [IsPad] p1: minsilkscreentomaskgap=0.025 clearancetoexposedcopper=TRUE
SolderMaskExpansion [All] p1: expansion=0.075
Width Width_1 [InNetClass('SE_CPWG')] p1: maxlimit=0.42 minlimit=0.39 preferedwidth=0.4
Width [All] p2: maxlimit=10 minlimit=0.125 preferedwidth=0.3
15 further rules are at their usual default settings.

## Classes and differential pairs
component class System_Overview-V4: TitleBlock7
component class Bluetooth: B3 C21 C22 C24 C106 D14 FB2 J19 R72 R73 R74 R75 R76 R77 R78 U12
net class Differential_RF: IN_N IN_P RFO_N RFO_P RX_N RX_P TX_N TX_P
component class "UHF RFID Reader": C1 C3 C4 C5 C6 C7 C12 C13 C14 C32 C34 C50 C51 C52 C54 C55 C56 C57 C58 C59 C60 C61 C62 C63 C64 C65 C66 C67 C69 C71 C72 C73 C74 C75 C76 C77 C78 C79 C80 C81 C82 C83 C84 C85 C86 C88 C89 C90 C91 C92 C93 C94 C110 C111 FB1 FB4 FB5 J9 L1 L2 L3 L4 L10 L15 R33 R54 R55 T3 T5 Title_Block_Antenna6 U4 U5 X3
component class "Power Amplifier": C15 C16 C17 C20 C70 C104 C105 C107 C108 C109 J1 J6 R10 R20 R21 R22 R23 R24 R25 R45 S1 T1 T2 Title_Block_Antenna4 U2 U3
component class "External Interfaces": D22 D23 D24 D25 D26 D27 D28 D29 D30 D31 D32 D33 D34 D35 D36 D37 D38 D39 D40 D41 D42 D43 D44 D45 D47 D48 D49 D50 D52 J2 J4 J7 J8 J10 J11 J12 J13 J14 J15 J16 P3 R4 R5 R19 R42 R46 Title_Block_Antenna2 TP1 TP2 TP3 TP4
component class "DC Supply": C38 C39 C40 C41 C42 C43 C44 C45 C46 C47 C48 C49 J5 J20 J21 R1 R2 R3 R27 R28 R29 R30 R31 R44 Title_Block_Antenna5 U9 U10 U11
component class "Carrier Cancellation": C18 C19 C37 C53 C68 C87 C95 J3 L11 L12 R26 R34 R35 T4 T6 Title_Block_Antenna7 U6 U7 U8
component class Controller: *3 B1 B2 BZ1 C2 C8 C9 C10 C11 C25 C26 C27 C28 C29 C31 D1 D2 D3 D4 D5 D6 D7 D8 D9 D10 D11 D12 D13 D15 D16 D17 FB3 R7 R8 R9 R11 R12 R13 R14 R15 R16 R17 R18 R36 R37 R38 R39 R40 R43 R50 R51 R52 R53 R56 R57 R58 R61 R64 R65 R66 R81 R82 R83 S5 TP5 TP6 TP7 TP8 TP9 TP10 TP11 TP12 TP13 TP14 TP15 TP16 TP17 U1 X1 Y2
net class SE_CPWG: LP_Filter_IN LP_Filter_OUT NetC32_1 NetC32_2 NetC35_1 NetC35_2 NetC36_1 NetC36_2 NetC37_1 NetC37_2 NetC107_1 NetC107_2 NetC108_1 NetC108_2 NetC109_1 NetC112_1 NetC112_2 NetJ1_IN NetJ1_OUT NetJ3_IN NetJ3_OUT NetL12_2 NetR22_2 NetR23_2 NetR24_2 NetT2_1 PA_OUT
component class Mechanical: SHIELD1 Title_Block_Antenna9
component class "Antenna Switch": C35 C36 C112 P4 P5 S2 Title_Block_Antenna7
component class "USB Interface": C23 C30 C33 C96 C97 C98 C99 C100 C101 C102 C103 D20 D21 FB7 P1 P2 R6 R41 R47 R86 R89 T8 U13 U14
differential pair D_ESD: +D_ESD_P -D_ESD_N
differential pair D_CON: +D_CON_P -D_CON_N
differential pair TX: +TX_P -TX_N
differential pair RX: +RX_P -RX_N
differential pair IN: +IN_P -IN_N
differential pair RFO: +RFO_P -RFO_N
differential pair D_CMC: +D_CMC_P -D_CMC_N

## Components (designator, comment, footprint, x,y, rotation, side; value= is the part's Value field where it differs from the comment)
B1 "RESET" SW_SPST_KMR211G 7.3,92.3 r180 top
B2 "Boot" SW_SPST_KMR211G 13.1,64.2 r180 top
B3 "BT_RESET" SW_SPST_KMR211G 65.875,80.8 r180 top
BZ1 "Buzzer" "PKMCS0909E Series" 13.5,81.7 r0 top
C1 "1p2F" C0402-RF#1 32.15,23.05 r270 top
C2 "0.47uF" NFM18PS 31,65.5 r180 top
C3 "1p2F" C0402-RF#1 32.15,25.3 r90 top
C4 "15pF" C0402-RF#1 34.9,23.7 r0 top
C5 "15pF" C0402-RF#1 34.9,24.65 r0 top
C6 "5p6F" C0402-RF#1 38.325,23.047 r270 top
C7 "5p6F" C0402-RF#1 38.325,25.298 r270 top
C8 "0.47uF" NFM18PS 23.63,67 r270 top
C9 "4p7F" C0402-RF#1 29.2,66.7 r180 top
C10 "4p7F" C0402-RF#1 27.6,66.7 r0 top
C11 "10uF" 2917(7343) 34.4,70.1 r90 top
C12 "120pF" C0201-RF 32.88,21.975 r180 top
C13 "2u2F" C0201-RF 27.4,20.1 r0 top
C14 "120pF" C0201-RF 33.08,26.3 r0 top
C15 "2u2F" C0201-RF 57.509,26.1 r180 top
C16 "0.47uF" NFM18PS 42.5,30.5 r270 top
C17 "2n2F" C0402-RF#1 62,26.2 r270 top
C18 "2u2F" C0201-RF 39.245,19.9 r0 top
C19 "2u2F" C0201-RF 52,17.53 r90 top
C20 "10uF" 2917(7343) 48.95,30.1 r0 top
C21 "0.47uF DNP" NFM18PS 57.6,92.3 r90 top
C22 "10uF DNP" 2917(7343) 53.8,84.1 r270 top
C23 "6u8F" 2917(7343) 29.4,78.2 r270 top
C24 "2u2F  DNP" C0201-RF 59.9,93.9 r270 top
C25 "100nF" C0402-RF#1 10.6,91.6 r90 top
C26 "2u2F" C0201-RF 23.9,65.6 r0 top
C27 "100nF" C0402-LLL 18.7,61.8 r90 top
C28 "100nF" C0402-LLL 18.7,55.3 r90 top
C29 "100nF" C0402-LLL 29.4,51.6 r180 top
C30 "2u2F" C0201-RF 21.5,72.93 r270 top
C31 "100nF" C0402-LLL 33.1,62.3 r270 top
C32 "82pF" C0402-RF#1 43.2,25.075 r180 top
C33 "2u2F" C0201-RF 25.545,69.9 r0 top
C34 "30 pF" C0201-RF 25.745,29.1 r0 top
C35 "82pF" C0402-RF#1 58.8,10.641 r0 top
C36 "82pF" C0402-RF#1 53.9,8.5 r225 top
C37 "3p6F" C0402-RF#1 46.446,17.2 r180 top
C38 "2u2F" C0402-RF#2 14,72.454 r90 top
C39 "0.47uF" NFM18PS 15.8,72 r180 top
C40 "2u2F" C0402-RF#2 9.8,72.454 r90 top
C41 "0.47uF" NFM18PS 8,72 r180 top
C42 "2u2F" C0402-RF#2 34.65,41.67 r90 top
C43 "0.47uF" NFM18PS 36.45,41.2 r180 top
C44 "2u2F" C0402-RF#2 30.45,41.67 r90 top
C45 "0.47uF" NFM18PS 28.65,41.2 r180 top
C46 "2u2F" C0402-RF#2 54.6,41.746 r270 top
C47 "0.47uF" NFM18PS 52.8,42.2 r0 top
C48 "2u2F" C0402-RF#2 58.8,41.746 r270 top
C49 "0.47uF" NFM18PS 60.6,42.2 r0 top
C50 "100nF" C0402-RF#2 18.446,35.1 r180 top
C51 "220nF" C0402-RF#1 23.4,32.154 r0 top
C52 "2u2F" C0201-RF 25.745,29.7 r180 top
C53 "120pF" C0201-RF 39.245,19.325 r0 top
C54 "82pF" C0402-RF#1 30.9,28.7 r45 top
C55 "3n9F" C0402-RF#2 14.7,18.3 r270 top
C56 "150pF" C0402-RF#1 15.9,21.2 r270 top
C57 "120pF" C0201-RF 30.65,26.4 r90 top
C58 "120pF" C0201-RF 27.8,29.25 r180 top
C59 "2u2F" C0201-RF 17.8,27.8 r180 top
C60 "120pF" C0201-RF 17.8,27.2 r180 top
C61 "2u2F" C0201-RF 17.8,26.6 r180 top
C62 "120pF" C0201-RF 17.8,26 r180 top
C63 "2u2F" C0201-RF 17.8,25.4 r180 top
C64 "120pF" C0201-RF 17.8,24.8 r180 top
C65 "82pF" C0402-RF#1 30.122,29.478 r45 top
C66 "2u2F" C0201-RF 29.9,20.95 r270 top
C67 "100nF" C0402-LLL 28.8,21 r270 top
C68 "120pF" C0201-RF 51.4,17.53 r90 top
C69 "100nF" C0402-LLL 19.8,27.7 r180 top
C70 "120pF" C0201-RF 57.509,26.8 r180 top
C71 "2u2F" C0201-RF 17.8,23.6 r180 top
C72 "30 pF" C0201-RF 17.8,24.2 r180 top
C73 "2u2F" C0201-RF 17.8,22.4 r180 top
C74 "30 pF" C0201-RF 17.8,23 r180 top
C75 "2u2F" C0201-RF 18.1,20.4 r180 top
C76 "120pF" C0201-RF 18.1,21 r180 top
C77 "100nF" C0402-LLL 28.8,19.9 r270 top
C78 "2u2F" C0201-RF 29.8,19.93 r270 top
C79 "10nF" C0201-ss 19.2,20.3 r225 top
C80 "10nF" C0201-ss 19.6,19.9 r225 top
C81 "10nF" C0201-ss 20,19.5 r225 top
C82 "10nF" C0201-ss 20.4,19.1 r225 top
C83 "100nF" C0402-LLL 24.725,19.4 r180 top
C84 "2u2F" C0201-RF 24.745,18.5 r180 top
C85 "2u2F" C0201-RF 26.2,18.325 r180 top
C86 "100nF" C0402-LLL 26.425,19.4 r0 top
C87 "2u2F" C0201-RF 47.9,20.78 r90 top
C88 "100nF" C0402-LLL 25.575,19.4 r0 top
C89 "2u2F" C0201-RF 25.475,18.2 r270 top
C90 "2u2F" C0201-RF 28.5,22.2 r90 top
C91 "0.47uF" NFM18PS 28.9,17.7 r0 top
C92 "10uF" 2917(7343) 33.3,16.5 r270 top
C93 "82pF" C0402-RF#1 22.975,16.4 r90 top
C94 "82pF" C0402-RF#1 23.975,16.4 r90 top
C95 "120pF" C0201-RF 47.3,20.78 r90 top
C96 "1uF" NFM21PC 33.9,81.275 r0 top
C97 "4u7F" C0603-ss 40.914,84 r0 top
C98 "100nF" C0402-LLL 35.9,86.9 r90 top
C99 "1uF" NFM21PC 19.7,73.2 r0 top
C100 "4pF" C0402-ss 18.2,93.4 r270 top
C101 "47pF" C0402-RF#1 24.975,78.575 r0 top
C102 "47pF" C0402-RF#1 23.075,78.575 r180 top
C103 "100nF" C0201-ss 23.005,75.4 r180 top
C104 "0.47uF" NFM18PS 44.45,40.55 r180 top
C105 "2u2F" C0201-RF 42.77,32 r0 top
C106 "100nF DNP" C0402-RF#2 62.625,80.429 r90 top
C107 "82pF" C0402-RF#2 52.9,25.075 r0 top
C108 "82pF" C0402-RF#2 56.2,27.6 r90 top
C109 "82pF" C0402-RF#2 55.7,22.55 r270 top
C110 "11pF" C0402-RF#1 25.695,35.654 r270 top
C111 "11pF" C0402-RF#1 20.295,35.654 r90 top
C112 "82pF" C0402-RF#2 53.7,12.275 r135 top
CE "Comment" LOGO_CE 51.41,57.767 r0 top
D1 "LED BL" LNJ947W8CRA 19.5,66 r90 top
D2 "LED BL" LNJ947W8CRA 72.8,23.5 r180 top
D3 "LED BL" LNJ947W8CRA 72.8,17.5 r180 top
D4 "LED BL" LNJ947W8CRA 72.8,25.5 r180 top
D5 "LED BL" LNJ947W8CRA 72.8,21.5 r180 top
D6 "LED BL" LNJ947W8CRA 3.8,1.2 r0 top
D7 "LED BL" LNJ947W8CRA 3.8,8.2 r0 top
D8 "LED BL" LNJ947W8CRA 3.8,6.45 r0 top
D9 "BAT60JFILM" SOD-232 28.4,70.5 r0 top
D10 "BAT60JFILM" SOD-232 36.1,63.8 r270 top
D11 "LED BL" LNJ947W8CRA 72.8,19.5 r180 top
D12 "`LED RD" LNJ947W8CRA 3.8,4.7 r0 top
D13 "`LED RD" LNJ947W8CRA 3.8,2.95 r0 top
D14 "LED BL DNP" LNJ947W8CRA 74.275,81.775 r90 top
D15 "`LED RD" LNJ947W8CRA 33.3,63.4 r0 top
D16 "LED BL" LNJ947W8CRA 58.4,1.2 r90 top
D17 "LED BL" LNJ947W8CRA 63.561,1.193 r90 top
D20 "TVS" DFN35P60X33-2N 29.4,85.2 r180 top
D21 "TVS" DFN35P60X33-2N 33.74,83.5 r270 top
D22 "TVS" DFN35P60X33-2N 5.2,20.9 r0 top
D23 "TVS" DFN35P60X33-2N 5.2,23.44 r0 top
D24 "TVS" DFN35P60X33-2N 5.2,25.98 r0 top
D25 "TVS" DFN35P60X33-2N 5.2,54.84 r0 top
D26 "TVS" DFN35P60X33-2N 5.2,52.3 r0 top
D27 "TVS" DFN35P60X33-2N 5.2,49.76 r0 top
D28 "TVS" DFN35P60X33-2N 65.5,59.2 r90 top
D29 "TVS" DFN35P60X33-2N 65.5,57.2 r90 top
D30 "TVS" DFN35P60X33-2N 65.5,56.2 r90 top
D31 "TVS" DFN35P60X33-2N 65.5,58.2 r90 top
D32 "TVS" DFN35P60X33-2N 65.5,60.2 r90 top
D33 "TVS" DFN35P60X33-2N 5.2,46.9 r0 top
D34 "TVS" DFN35P60X33-2N 5.2,44.36 r0 top
D35 "TVS" DFN35P60X33-2N 5.2,41.82 r0 top
D36 "TVS" DFN35P60X33-2N 5.2,39.28 r0 top
D37 "TVS" DFN35P60X33-2N 5.2,36.74 r0 top
D38 "TVS" DFN35P60X33-2N 5.2,34.2 r0 top
D39 "TVS" DFN35P60X33-2N 41.98,90.8 r270 top
D40 "TVS" DFN35P60X33-2N 47.06,90.8 r270 top
D41 "TVS" DFN35P60X33-2N 39.44,90.8 r270 top
D42 "TVS" DFN35P60X33-2N 44.52,90.8 r270 top
D43 "TVS" DFN35P60X33-2N 36.9,90.8 r270 top
D44 "TVS" DFN35P60X33-2N 49.6,90.8 r270 top
D45 "TVS" DFN35P60X33-2N 70.9,38 r180 top
D47 "TVS" DFN35P60X33-2N 5.2,66.9 r0 top
D48 "TVS" DFN35P60X33-2N 5.2,64.36 r0 top
D49 "TVS" DFN35P60X33-2N 5.2,61.82 r0 top
D50 "TVS" DFN35P60X33-2N 5.2,59.28 r0 top
D52 "TVS" DFN35P60X33-2N 5.2,29.9 r0 top
ESD "Comment" Logo_ESD 23.87,2.877 r0 top
FB1 "330R" FB0402-RF 29.5,22.03 r0 top
FB2 "1k DNP" L0402-RF 58.7,94.27 r0 top
FB3 "1k" L0402-RF 25.1,68.3 r180 top
FB4 "1k" L0402-RF 18.9,33.7 r270 top
FB5 "1k" L0402-RF 27.5,18.8 r270 top
FB7 "31 Ohm" NFZ32BW310HN11 38.05,81.275 r0 top
J1 "COAX JACK" MS-156HF_SAW 34.3,33.6 r315 top
J2 "Header3_THMD DNP" PLUG_THMD_STRIP3 3.2,16 r270 top
J3 "COAX JACK" MS-156HF 48.725,11.095 r90 top
J4 "Header1_THMD - DNP" PLUG_THMD_STRIP1 72.725,38 r0 top
J5 "Header3_THMD DNP" PLUG_THMD_STRIP3 3.3,75.2 r270 top
J6 "COAX JACK" MS-156HF 56.2,30.8 r180 top
J7 "Header4_THMD - DNP" PLUG_THMD_STRIP4 3.251,66.9 r270 top
J8 "Header3_THMD DNP" PLUG_THMD_STRIP3 72.75,29.5 r90 top
J9 "COAX JACK" MS-156HF 49,25.075 r270 top
J10 "Header3_THMD DNP" PLUG_THMD_STRIP3 3.2,20.9 r90 top
J11 "Header1_THMD - DNP" PLUG_THMD_STRIP1 3.2,29.9 r270 top
J12 "Header6_THMD DNP" PLUG_THMD_STRIP6 3.2,46.9 r270 top
J13 "Header3_THMD DNP" PLUG_THMD_STRIP3 3.2,54.84 r270 top
J14 "Header8_THMD DNP" PLUG_THMD_STRIP8 36.9,92.75 r0 top
J15 "Header3_THMD DNP" PLUG_THMD_STRIP3 72.725,67.5 r90 top
J16 "Header1_THMD - DNP" PLUG_THMD_STRIP1 3.3,83.7 r90 top
J19 "Jumper2_THMD  DNP" "PLUG_THMD_STRIP2 - DNP" 72.725,76.4 r90 top
J20 "Header3_THMD DNP" PLUG_THMD_STRIP3 31.36,48.05 r0 top
J21 "Header3_THMD DNP" PLUG_THMD_STRIP3 72.725,46.65 r270 top
L1 "30nH" L0402-RF 33.35,23.05 r270 top
L2 "30nH" L0402-RF 33.35,25.3 r270 top
L3 "30nH" L0402-RF 28.475,28.375 r315 top
L4 "30nH" L0402-RF 29.775,27.05 r315 top
L10 "3n6H" L0402-RF 36.775,24.65 r180 top
L11 "6n8H" L0402-RF 47.725,16.746 r90 top
L12 "5n6H" L0402-RF 42.775,17.654 r270 top
L15 "3n6H" L0402-RF 36.775,23.7 r0 top
P1 "µUSB" "µUSB Molex" 23.7,91.7 r180 top
P2 "Header 2H" "PLUG_THMD_STRIP2 - 90°" 31.2,85.2 r0 top
P3 "TC2050-IDC-FP" TC2050-IDC-FP 70.185,61.407 r270 top
P4 "SMB JACK STR 50OHM EDGE MNT" 903-723J-51S 53,3.8 r180 top
P5 "SMB JACK STR 50OHM EDGE MNT" 903-723J-51S 69,3.8 r180 top
R1 "0R" R0603-ss 1,71.3 r90 top
R2 "0R" R0603-ss 35.175,50.4 r180 top
R3 "0R" R0603-ss 75.05,42.75 r90 top
R4 "220" R0402-RF 64.3,58 r180 top
R5 "220" R0402-RF 64.3,60 r180 top
R6 "0R" R0402-RF 25.7,69.2 r180 top
R7 "0R" R0402-RF 16.3,61.1 r0 top
R8 "0R" R0402-RF 16.3,59.9 r0 top
R9 "0R" R0402-RF 16.3,58.7 r0 top
R10 "0R" R0402-RF 43.2,39.4 r90 top
R11 "0R" R0402-RF 16.3,57.5 r0 top
R12 "0R" R0402-RF 26.6,50 r90 top
R13 "0R" R0402-RF 27.8,50 r90 top
R14 "220" R0402-RF 20.5,66 r90 top
R15 "220" R0402-RF 35.7,56.3 r0 top
R16 "10k" R0402-RF 9.7,64.2 r90 top
R17 "220" R0402-RF 35.7,52.7 r0 top
R18 "220" R0402-RF 35.7,57.5 r0 top
R19 "220" R0402-RF 64.3,59 r180 top
R20 "0R" R0402-RF 42.3,39.4 r90 top
R21 "100R" R0402-RF 42.046,32.9 r180 top
R22 "51.1R" R0402-RF 55.1,14.8 r90 top
R23 "52.3R" R0402-RF 58.425,22.6 r0 top
R24 "249R" R0402-RF 58.879,20.5 r270 top
R25 "62R" R0402-RF 59.333,21.7 r180 top
R26 "75R" R0402-RF 41.75,17.654 r270 top
R27 "10k" R0402-RF 13.3,71 r180 top
R28 "35k7" R0402-RF 32.05,40.3 r180 top
R29 "10k" R0402-RF 33.85,40.3 r180 top
R30 "42.2k" R0402-RF 57.154,43.2 r0 top
R31 "10k" R0402-RF 55.2,43.2 r0 top
R33 "15k" R0402-RF 14.7,21.2 r90 top
R34 "0R" R0402-RF 44.754,17.2 r180 top
R35 "100R DNP" R0402-RF 40.625,17.654 r270 top
R36 "0R" R0402-RF 28.398,72.2 r0 top
R37 "0R" R0402-RF 33.4,64.4 r0 top
R38 "0R" R0402-RF 21.8,48.1 r270 top
R39 "0R" R0402-RF 23,48.1 r270 top
R40 "0R" R0402-RF 24.2,48.1 r270 top
R41 "27R" R0402-RF 24.525,77.175 r270 top
R42 "220" R0402-RF 64.3,57 r180 top
R43 "0R" R0402-RF 35.7,58.7 r180 top
R44 "31k6" R0402-RF 11.404,71 r180 top
R45 "62R" R0402-RF 59.333,19.3 r180 top
R46 "220" R0402-RF 64.3,56 r180 top
R47 "27R" R0402-RF 23.525,77.175 r270 top
R50 "220" R0402-RF 35.7,55.1 r0 top
R51 "220" R0402-RF 16.4,46.5 r180 top
R52 "220" R0402-RF 16.4,51.3 r180 top
R53 "220" R0402-RF 16.4,50.1 r180 top
R54 "0R DNP" R0402-RF 23.9,33.4 r90 top
R55 "0R DNP" R0402-RF 24.975,30.7 r270 top
R56 "0R" R0402-RF 21.5,66 r270 top
R57 "0R" R0402-RF 19,63.1 r270 top
R58 "0R" R0402-RF 16.3,56.3 r180 top
R61 "10k" R0402-RF 26.1,66.4 r270 top
R64 "220" R0402-RF 35.7,53.9 r0 top
R65 "220" R0402-RF 16.4,48.9 r180 top
R66 "220" R0402-RF 16.4,47.7 r180 top
R72 "0R  DNP" R0402-RF 61.1,83.45 r270 top
R73 "0R DNP" R0402-RF 60.125,83.8 r270 top
R74 "10k  DNP" R0402-RF 57.4,83.8 r90 top
R75 "0R DNP" R0402-RF 59.2,83.8 r270 top
R76 "0R  DNP" R0402-RF 58.25,83.825 r270 top
R77 "220 DNP" R0402-RF 72.712,82.8 r270 top
R78 "10k  DNP" R0402-RF 70.5,74.5 r0 top
R81 "220" R0402-RF 34.7,62.9 r90 top
R82 "220" R0402-RF 58.4,4.3 r270 top
R83 "220" R0402-RF 63.561,4.3 r270 top
R86 "20R" R0402-RF 43.1,84 r180 top
R89 "0R" R0402-RF 18.2,91 r270 top
S1 "SP2T" SKY13431-374LF 55.7,24.35 r90 top
S2 "SP2T" SKY13431-374LF 55.175,10.8 r315 top
SHIELD1 "CRS-50.80X38.1" "RF Shield - 50.8 x 38.1 mm" 12.95,6.55 r0 top locked
"ST25 Logo" "Comment" Logo_ST25 70.3,11.6 r0 top
T1 "LOWPASS FILTER" JTI-0900LP15B0063 55.7,20.6 r270 top
T2 "20 dB Dir Coupler" DC0710J5010AHF 55.8,16.5 r45 top
T3 "Balun" JTI-0900BL15C050 40.325,24.175 r270 top
T4 "10dB Dir Coupler" DC0710J5010AHF 52,13.8 r270 top
T5 "BD0810J50100A00" BD0810J50100AHF 32.3,30.9 r315 top
T6 "BD0810J50100A00" BD0810J50100AHF 45.5,10.6 r270 top
T8 "744231091" 744231091 24.025,80.825 r270 top
TP1 "Testpoint" TP#1 24,31.1 r90 top
TP2 "Testpoint" TP#1 14.7,19.75 r90 top
TP3 "Testpoint" TP#1 40.4,32.9 r90 top
TP4 "Testpoint" TP#1 60,30.5 r90 top
TP5 "Testpoint" TP#1 18.3,66.441 r90 top
TP6 "Testpoint" TP#1 71,23.5 r90 top
TP7 "Testpoint" TP#1 71,21.5 r90 top
TP8 "Testpoint" TP#1 5.5,1.2 r90 top
TP9 "Testpoint" TP#1 71,19.5 r90 top
TP10 "Testpoint" TP#1 71,17.5 r90 top
TP11 "Testpoint" TP#1 71,25.5 r90 top
TP12 "Testpoint" TP#1 5.5,8.2 r90 top
TP13 "Testpoint" TP#1 5.55,6.45 r90 top
TP14 "Testpoint" TP#1 58.4,2.767 r90 top
TP15 "Testpoint" TP#2 92.315,2.215 r90 top
TP16 "Testpoint" TP#1 5.5,4.7 r90 top
TP17 "Testpoint" TP#1 5.55,2.95 r90 top
U1 "STM32L476RGT6" LQFP64-10x10mm 25.9,58.8 r270 top
U2 "TQP9107" TQP9107 44,35.8 r180 top
U3 "Log Detect" MAX4003 59.854,26.2 r90 top
U4 "TCXO 20.000MHZ" "3.2 x 2.5 mm SMD" 20.4,31.474 r0 top
U5 "ST25RU3993" ST25RU3993_QFN48_0.5mm_pitch 24.225,24.175 r90 top
U6 "PE64906MLAA-Z" PE62304 49.4,18.175 r90 top
U7 "PE64906MLAA-Z" PE62304 45.6,19.7 r180 top
U8 "PE64906MLAA-Z" PE62304 38,17.7 r180 top
U9 "LD39100PUR" LD39100PUR 11.9,73.3 r180 top
U10 "LD39100PUR" LD39100PUR 32.55,42.5 r180 top
U11 "LD39100PUR" LD39100PUR 56.7,40.9 r0 top
U12 "SPBT3.0DP2  DNP" SPBT3.0DP2 74.3,85.9 r90 top
U13 "FT231XQ-R" FT231XQ 24.275,72.7 r180 top
U14 "USB6B1" SO-8 24.025,86.5 r270 top
X1 "NX3215SA-32.768K-STD-MUA-14" NX3215SA-32.768K-STD-MUA-8 28.4,68.3 r180 top
X3 "20 MHZ" NX3225SA 22.995,36.054 r0 top

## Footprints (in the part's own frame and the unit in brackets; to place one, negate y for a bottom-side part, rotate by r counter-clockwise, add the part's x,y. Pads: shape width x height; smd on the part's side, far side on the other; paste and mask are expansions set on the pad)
"3.2 x 2.5 mm SMD" [mm] "Temperature Compensated Crystal Oscillator"
  rect 1x0.9 smd paste+0 mask+0: 1(-1.2,-0.9) 2(1.2,-0.9) 3(1.2,0.9) 4(-1.2,0.9)
  silkscreen extent -1.88,-1.45 1.88,1.43, body extent -1.65,-1.33 1.65,1.3, height 0.7
903-723J-51S [mm] "Amphenol - SOCKET_TH_SMB_EDGE"
  rect 1.2x3.18 smd paste+0 mask+0.15: 1(0,2.22)
  rect 1.78x3.3 smd paste+0 mask+0.15: 2(-2.96,2.16) 3(2.96,2.16)
  rect 1.78x2.3 smd paste+0 mask+0.15: 4(-2.96,-1.615) 5(2.96,-1.615)
  body extent -7.37,-2.17 3.49,12.94, height 4.57
2917(7343) [mm] "Chip Capacitor, 2-Leads, Body 7,30x4,30mm, IPC Medium Density"
  rect 2.4x2.4 smd: 1(-3.2,0) 2(3.2,0)
  silkscreen extent -3.55,-3.36 1.6,2.15, body extent -3.86,-2.25 3.85,2.25, height 1.91
744231091 [mm] "SMD Common Mode Noise Suppressor"
  rect 0.9x0.4 smd paste+0 mask+0: 1(-0.85,-0.4) 2(0.85,-0.4) 3(0.85,0.4) 4(-0.85,0.4)
  silkscreen extent -1.1,-0.71 1.1,0.7, body extent -1,-0.6 1,0.6, height 0.7
BD0810J50100AHF [mm] "RF Balun 800MHz ~ 1GHz 50 / 100 Ohm 0805"
  rect 0.27x0.41 smd mask+0.04: 1(-0.495,0.66) 3(-0.495,-0.66) 4(0.495,-0.66) 6(0.495,0.66)
  rect 0.33x0.41 smd mask+0.04: 2(-0.495,0) 5(0.495,0)
  silkscreen extent -0.8,-1.19 0.8,1.18, body extent -0.65,-1.03 0.65,1.03, height 0.86
C0201-RF [mm]
  rrect50% 0.24x0.33 smd paste-3 mask+0.005: 1(-0.255,0) 2(0.255,0)
  body extent -0.3,-0.15 0.3,0.15, height 0.23
C0201-ss [mm]
  rect 0.25x0.33 smd paste+0 mask+0.01: 1(-0.27,0) 2(0.27,0)
  body extent -0.3,-0.15 0.3,0.15, height 0.23
C0402-LLL [mm]
  rect 0.2x0.9 smd paste+0 mask+0: 1(-0.2,0) 2(0.2,0)
  silkscreen extent -0.43,-0.61 0.43,0.6, body extent -0.26,-0.51 0.25,0.51, height 0.31
C0402-RF#1 [mil]
  rect 15.75x22 smd paste+0 mask+0: 1(-21,0) 2(21,0)
  body extent -22,-11 22,11, height 12
C0402-RF#2 [mil]
  rect 15.75x22 smd paste+0 mask+0: 1(-17.87,0) 2(17.87,0)
  body extent -22,-11 22,11, height 12
C0402-ss [mil]
  rect 22x22 smd paste+0 mask+0: 1(-21,0) 2(21,0)
  body extent -27,-11 27,11, height 12
C0603-ss [mil]
  rect 32x38 smd paste+0 mask+0.39: 1(-28,0) 2(28,0)
  body extent -38,-19 40,19, height 20
DC0710J5010AHF [mm] "Directional Coupler"
  rect 0.33x0.41 smd mask+0.04: 1(-0.495,0.66) 2(-0.495,0) 3(-0.495,-0.66) 4(0.495,-0.66) 5(0.495,0) 6(0.495,0.66)
  silkscreen extent -1.35,-1.19 0.8,1.26, body extent -0.65,-1.03 0.65,1.03, height 0.86
DFN35P60X33-2N [mm] "DFN, 2-Leads, Body 0,30x0,60mm, Pitch 0,35mm, IPC Medium Density"
  rect 0.243x0.3 smd mask+0.035: 1(-0.206,0) 2(0.206,0)
  silkscreen extent -0.38,0.53 -0.28,0.62, body extent -0.33,-0.18 0.33,0.18, height 0.33
FB0402-RF [mil] "Ferrite Bead"
  rect 15.75x22 smd paste+0 mask+0: 1(-21,0) 2(21,0)
  body extent -22,-11 22,11, height 12
FT231XQ [mm] "USB TO FULL HANDSHAKE UART IC"
  oval 0.9x0.25 smd: 1(-1.875,1) 2(-1.875,0.5) 3(-1.875,0) 4(-1.875,-0.5) 5(-1.875,-1) 11(1.875,-1) 12(1.875,-0.5) 13(1.875,0) 14(1.875,0.5) 15(1.875,1)
  oval 0.25x0.9 smd: 6(-1,-1.875) 7(-0.5,-1.875) 8(0,-1.875) 9(0.5,-1.875) 10(1,-1.875) 16(1,1.875) 17(0.5,1.875) 18(0,1.875) 19(-0.5,1.875) 20(-1,1.875)
  rect 1.98x1.98 smd: 21(0,0)
  silkscreen extent -2.68,-2.15 2.15,2.15, body extent -2.01,-2.01 2.01,2.01, height 0.78
JTI-0900BL15C050 [mm] "900 MHz Balun 1:1"
  rect 1x0.3 smd mask+0.07: 1(-0.9,0.66) 2(-0.9,0) 3(-0.9,-0.65) 4(0.9,-0.65) 5(0.9,0) 6(0.9,0.66)
  silkscreen extent -1.4,-1.12 0.74,1.35, body extent -0.64,-1.02 0.65,1.02, height 0.86
JTI-0900LP15B0063 [mm] "900 MHz Low Pass Filter"
  rect 0.35x1 smd mask+0.05: 1(-0.65,-0.9) 2(0,-0.9) 3(0.65,-0.9) 5(0.65,0.9) 6(0,0.9) 7(-0.65,0.9)
  rect 1x0.27 smd mask+0.05: 4(1.175,0) 8(-1.175,0)
  Top Layer region: -0.511,-0.399 -0.511,1.4 -0.325,1.4 -0.325,0.25 0,0.25 0,-0.25 -0.325,-0.25 -0.325,-1.4 -0.511,-1.4
  Top Layer region: 0.51,0.399 0.51,-1.4 0.325,-1.4 0.325,-0.25 0,-0.25 0,0.25 0.325,0.25 0.325,1.4 0.51,1.4
  Top Layer region: -0.325,1.4 -0.325,1.55 0.325,1.55 0.325,1.4 0.51,1.4 0.51,1.725 -0.511,1.725 -0.511,1.4
  Top Layer region: 0.325,-1.4 0.325,-1.55 -0.325,-1.55 -0.325,-1.4 -0.51,-1.4 -0.51,-1.725 0.511,-1.725 0.511,-1.4
  silkscreen extent -1.5,-1.07 1.08,0.7, body extent -1.08,-0.7 1.08,0.7, height 0.96
L0402-RF [mil]
  rect 15.75x22 smd paste+0 mask+0: 1(-21,0) 2(21,0)
  body extent -22,-11 22,11, height 12
LD39100PUR [mm] "1 A, low quiescent current, low-noise voltage regulator"
  rrect10% 2.5x1.75 smd mask+0.05: 0(0,0)
  oval 0.35x0.5 smd mask+0.05: 1(-0.95,-1.3) 2(0,-1.3) 3(0.95,-1.3) 4(0.95,1.3) 5(0,1.3) 6(-0.95,1.3)
  silkscreen extent -1.94,-1.3 -1.78,-1.14, body extent -1.5,-1.55 1.5,1.55, height 0.75
LNJ947W8CRA [mm] "Blue 472nm LED Indication - Discrete 2.9V"
  rect 0.45x0.65 smd paste+0 mask+0: 1(-0.52,0) 2(0.52,0)
  silkscreen extent 0.98,0.13 0.98,0.43, body extent -0.55,-0.28 0.55,0.28, height 0.31
LOGO_CE [mm] "Silk only"
  silkscreen extent -2.27,-1.96 2.8,1.78
Logo_ESD [mm] "Silk only"
  silkscreen extent -3.61,-2.24 3.34,3.67
Logo_ST25 [mm] "Silk Only"
  silkscreen extent -4.44,-4.19 4.5,4.7
LQFP64-10x10mm [mm]
  rect 1.194x0.305 smd: 1(-5.75,3.75) 2(-5.75,3.25) 3(-5.75,2.75) 4(-5.75,2.25) 5(-5.75,1.75) 6(-5.75,1.25) 7(-5.75,0.75) 8(-5.75,0.25) 9(-5.75,-0.25) 10(-5.75,-0.75) 11(-5.75,-1.25) 12(-5.75,-1.75) 13(-5.75,-2.25) 14(-5.75,-2.75) 15(-5.75,-3.25) 16(-5.75,-3.75) 33(5.75,-3.75) 34(5.75,-3.25) 35(5.75,-2.75) 36(5.75,-2.25) 37(5.75,-1.75) 38(5.75,-1.25) 39(5.75,-0.75) 40(5.75,-0.25) 41(5.75,0.25) 42(5.75,0.75) 43(5.75,1.25) 44(5.75,1.75) 45(5.75,2.25) 46(5.75,2.75) 47(5.75,3.25) 48(5.75,3.75)
  rect 0.305x1.194 smd: 17(-3.75,-5.75) 18(-3.25,-5.75) 19(-2.75,-5.75) 20(-2.25,-5.75) 21(-1.75,-5.75) 22(-1.25,-5.75) 23(-0.75,-5.75) 24(-0.25,-5.75) 25(0.25,-5.75) 26(0.75,-5.75) 27(1.25,-5.75) 28(1.75,-5.75) 29(2.25,-5.75) 30(2.75,-5.75) 31(3.25,-5.75) 32(3.75,-5.75) 49(3.75,5.75) 50(3.25,5.75) 51(2.75,5.75) 52(2.25,5.75) 53(1.75,5.75) 54(1.25,5.75) 55(0.75,5.75) 56(0.25,5.75) 57(-0.25,5.75) 58(-0.75,5.75) 59(-1.25,5.75) 60(-1.75,5.75) 61(-2.25,5.75) 62(-2.75,5.75) 63(-3.25,5.75) 64(-3.75,5.75)
  silkscreen extent -5.85,-5.13 5.13,5.13, body extent -6.07,-6.07 6.07,6.07, height 1.63
MAX4003 [mm] "µmax"
  oval 1.35x0.4 smd: 1(-2.15,0.975) 2(-2.15,0.325) 3(-2.15,-0.325) 4(-2.15,-0.975) 5(2.15,-0.975) 6(2.15,-0.325) 7(2.15,0.325) 8(2.15,0.975)
  silkscreen extent -2.35,-1.55 1.15,1.9, body extent -1.55,-1.55 1.55,1.55, height 1.1
MS-156HF [mm] "Subminiature Coaxial Switch"
  rect 0.8x2.65 smd paste+0 mask+0.051: G1(1.1,0) G2(-1.1,0)
  rect 0.55x0.55 smd paste-0.3 mask+0.051: IN(0,-1.525)
  rect 0.55x0.7 smd paste-0.3 mask+0.051: OUT(0,1.25)
  body extent -1.36,-1.35 1.34,1.35, height 1.56
MS-156HF_SAW [mm] "Coax swappable with SAW"
  rect 0.6x1.5 smd paste-0.065 mask+0.1: G1(-1.2,-0.75)
  rect 0.6x0.75 smd paste-0.065 mask+0.1: G1(-1.2,1.125) G2(1.2,-1.125) G2(1.2,1.125) IN(0,-1.125) OUT(0,1.125)
  silkscreen extent -2,-1.66 1.66,1.66, body extent -1.35,-1.35 1.35,1.35, height 1.56
NFM18PS [mm] "Feed Through Capacitor"
  rect 0.35x0.35 smd paste+0 mask+0: 1(-0.825,0) 3(0.825,0)
  rect 0.8x0.4 smd paste+0 mask+0: 2(0,0.625) 2(0,-0.625)
  Top Layer region: -0.4,-1.275 0.4,-1.275 0.4,-0.625 -0.4,-0.625
  Top Layer region: -0.4,0.625 0.4,0.625 0.4,1.275 -0.4,1.275
  Top Layer region: -0.3,-0.2 0.3,-0.2 0.3,0.2 -0.3,0.2
  Top Layer region: -0.65,-0.174 -0.6,-0.15 -0.6,0.15 -0.65,0.174 -0.8,0
  Top Layer region: 0.65,0.175 0.6,0.15 0.6,-0.15 0.65,-0.175 0.825,0
  Top Layer region: -0.4,0.425 -0.4,0.3 -0.3,0.2 0.3,0.2 0.4,0.3 0.4,0.425 0,0.625
  Top Layer region: 0.4,-0.425 0.4,-0.3 0.3,-0.2 -0.3,-0.2 -0.4,-0.3 -0.4,-0.425 0,-0.625
  body extent -0.82,-0.43 0.82,0.43, height 0.6
NFM21PC [mm] "Feed Through Capacitor"
  rect 0.6x0.8 smd paste+0 mask+0: 1(-1,0) 3(1,0)
  rect 0.6x0.65 smd paste+0 mask+0: 2(0,-0.625) 2(0,0.625)
  Top Layer region: -0.3,-0.3 0.3,-0.3 0.3,0.3 -0.3,0.3
  Top Layer region: -0.3,0.95 0.3,0.95 0.3,1.45 -0.3,1.45
  Top Layer region: 0.3,-0.95 -0.3,-0.95 -0.3,-1.45 0.3,-1.45
  body extent -1.13,-0.65 1.13,0.65, height 0.85
NFZ32BW310HN11 [mm] "Chip Inductor, 2-Leads, Body 3.20x2.50mm, IPC Medium Density"
  rect 1.3x2.5 smd: 1(-1.75,0) 2(1.75,0)
  silkscreen extent -0.05,-1.26 0.05,1.26, body extent -1.75,-1.35 1.75,1.35, height 1.7
NX3215SA-32.768K-STD-MUA-8 [mm] "g 32,768kHz, ±20ppm Kristall, 12,5pF, 70 kOhm"
  rect 1x1.8 smd: 1(-1.25,0) 2(1.25,0)
  body extent -1.6,-0.75 1.6,0.75, height 0.7
NX3225SA [mm] "20 MHz Crystal Oscillator"
  rect 1.4x1.2 smd paste+0 mask+0: 1(-1.1,-0.8) 2(1.1,-0.8) 3(1.1,0.8) 4(-1.1,0.8)
  silkscreen extent -1.88,-1.45 1.88,1.43, body extent -1.65,-1.3 1.65,1.3, height 1.1
PE62304 [mm] "Digitally Tunable Capacitor for GSM/WCDMA"
  rect 0.45x0.25 smd mask+0.05: 1(-0.975,0.75) 2(-0.975,0.25) 3(-0.975,-0.25) 4(-0.975,-0.75) 6(0.975,-0.75) 7(0.975,-0.25) 8(0.975,0.25) 9(0.975,0.75)
  rect 0.25x0.45 smd mask+0.05: 5(0,-0.975) 10(0,0.975)
  rect 0.95x0.95 smd mask+0.05: 10(0,0)
  silkscreen extent -1.33,-1.04 1.04,1.28, body extent -1,-1.07 1,0.92, height 0.6
"PKMCS0909E Series" [mm] "Murata Sounder"
  rect 1.3x3.4 smd: 1(-4.35,0) 2(4.35,0)
  silkscreen extent -5.32,-4.6 1.6,4.6, body extent -4.5,-4.5 4.5,4.5, height 1.9
PLUG_THMD_STRIP1 [mm]
  rect 1.6x1.6 / inner round 1.524 / far side rect 1.6x1.6 hole 1 paste+0 mask+0: 1(0,0)
  silkscreen extent -1.27,-1.27 1.27,1.12, body extent -1.27,-1.27 1.27,1.27, height 8.57
"PLUG_THMD_STRIP2 - 90°" [mm]
  rect 1.6x1.6 / inner round 1.524 / far side rect 1.6x1.6 hole 1 paste+0 mask+0: 1(0,0)
  round 1.6 / inner round 1.524 / far side round 1.6 hole 1 paste+0 mask+0: 2(2.54,0)
  silkscreen extent -1.27,-1.27 3.81,4.19, body extent -1.27,-0.35 3.81,10.01, height 2.54
"PLUG_THMD_STRIP2 - DNP" [mm]
  rect 1.6x1.6 / inner round 1.524 / far side rect 1.6x1.6 hole 1 paste+0 mask+0: 1(0,0)
  round 1.6 / inner round 1.524 / far side round 1.6 hole 1 paste+0 mask+0: 2(2.54,0)
  silkscreen extent -1.27,-1.27 3.81,1.27
PLUG_THMD_STRIP3 [mm]
  rect 1.6x1.6 / inner round 1.524 / far side rect 1.6x1.6 hole 1 paste+0 mask+0: 1(0,0)
  round 1.6 / inner round 1.524 / far side round 1.6 hole 1 paste+0 mask+0: 2(2.54,0) 3(5.08,0)
  silkscreen extent -1.27,-1.27 6.35,1.27, body extent -1.27,-1.27 6.35,1.27, height 8.57
PLUG_THMD_STRIP4 [mm]
  rect 1.6x1.6 / inner round 1.524 / far side rect 1.6x1.6 hole 1 paste+0 mask+0: 1(0,0)
  round 1.6 / inner round 1.524 / far side round 1.6 hole 1 paste+0 mask+0: 2(2.54,0) 3(5.08,0) 4(7.62,0)
  silkscreen extent -1.27,-1.27 8.89,1.27, body extent -1.27,-1.27 8.89,1.27, height 8.57
PLUG_THMD_STRIP6 [mm]
  rect 1.6x1.6 / inner round 1.524 / far side rect 1.6x1.6 hole 1 paste+0 mask+0: 1(0,0)
  round 1.6 / inner round 1.524 / far side round 1.6 hole 1 paste+0 mask+0: 2(2.54,0) 3(5.08,0) 4(7.62,0) 5(10.16,0) 6(12.7,0)
  silkscreen extent -1.27,-1.27 13.97,1.27, body extent -1.27,-1.27 13.97,1.27, height 8.57
PLUG_THMD_STRIP8 [mm]
  rect 1.6x1.6 / inner round 1.524 / far side rect 1.6x1.6 hole 1 paste+0 mask+0: 1(0,0)
  round 1.6 / inner round 1.524 / far side round 1.6 hole 1 paste+0 mask+0: 2(2.54,0) 3(5.08,0) 4(7.62,0) 5(10.16,0) 6(12.7,0) 7(15.24,0) 8(17.78,0)
  silkscreen extent -1.27,-1.27 19.05,1.27, body extent -1.27,-1.27 19.05,1.27, height 8.57
R0402-RF [mil]
  rect 15.75x22 smd paste+0 mask+0: 1(-21,0) 2(21,0)
  body extent -22,-11 22,11, height 12
R0603-ss [mil]
  rect 32x38 smd paste+0 mask+0.39: 1(-28,0) 2(28,0)
  body extent -38,-19 40,19, height 20
"RF Shield - 50.8 x 38.1 mm" [mm] "2118732-2"
  rect 0.8x0.8 smd: 1(0.4,0.4) 2(0.4,5.95) 3(0.4,11.95) 4(0.4,17.95) 5(0.4,23.95) 6(0.4,29.95) 7(0.4,38.5) 8(6.3,38.5) 9(12.3,38.5) 10(18.3,38.5) 11(24.3,38.5) 12(30.3,38.5) 13(36.3,38.5) 14(42.3,38.5) 15(51.2,38.5) 16(51.2,29.95) 17(51.2,23.95) 18(51.2,17.95) 19(51.2,11.95) 20(51.2,5.95) 21(51.2,0.4) 22(42.3,0.4) 23(36.3,0.4) 24(30.3,0.4) 25(24.3,0.4) 26(18.3,0.4) 27(12.3,0.4) 28(6.3,0.4)
  Top Layer region: 35.9,38.1 39.7,38.1 39.7,38.9 35.9,38.9
  Top Layer region: 29.9,38.1 33.7,38.1 33.7,38.9 29.9,38.9
  Top Layer region: 23.9,38.1 27.7,38.1 27.7,38.9 23.9,38.9
  Top Layer region: 17.9,38.1 21.7,38.1 21.7,38.9 17.9,38.9
  Top Layer region: 11.9,38.1 15.7,38.1 15.7,38.9 11.9,38.9
  Top Layer region: 5.9,38.1 9.7,38.1 9.7,38.9 5.9,38.9
  Top Layer region: 41.9,38.1 45.7,38.1 45.7,38.9 41.9,38.9
  Top Layer region: 50.8,29.55 51.6,29.55 51.6,33.35 50.8,33.35
  Top Layer region: 50.8,23.55 51.6,23.55 51.6,27.35 50.8,27.35
  Top Layer region: 50.8,17.55 51.6,17.55 51.6,21.35 50.8,21.35
  Top Layer region: 50.8,11.55 51.6,11.55 51.6,15.35 50.8,15.35
  Top Layer region: 50.8,5.55 51.6,5.55 51.6,9.35 50.8,9.35
  Top Layer region: 41.9,0 45.7,0 45.7,0.8 41.9,0.8
  Top Layer region: 0,23.55 0.8,23.55 0.8,27.35 0,27.35
  Top Layer region: 0,17.55 0.8,17.55 0.8,21.35 0,21.35
  Top Layer region: 0,11.55 0.8,11.55 0.8,15.35 0,15.35
  Top Layer region: 0,5.55 0.8,5.55 0.8,9.35 0,9.35
  Top Layer region: 5.9,0 9.7,0 9.7,0.8 5.9,0.8
  Top Layer region: 11.9,0 15.7,0 15.7,0.8 11.9,0.8
  Top Layer region: 17.9,0 21.7,0 21.7,0.8 17.9,0.8
  Top Layer region: 23.9,0 27.7,0 27.7,0.8 23.9,0.8
  Top Layer region: 29.9,0 33.7,0 33.7,0.8 29.9,0.8
  Top Layer region: 35.9,0 39.3,0 39.3,0.8 35.9,0.8
  Top Layer region: 0,29.55 0.8,29.55 0.8,33.35 0,33.35
  Top Layer region: 51.6,38.899 51.6,35.55 50.8,35.55 50.8,38.1 47.899,38.1 47.899,38.899
  Top Layer region: 51.6,0 51.6,3.3 50.8,3.3 50.8,0.8 47.9,0.8 47.9,0
  Top Layer region: 0,0 0,3.35 0.8,3.35 0.8,0.8 3.7,0.8 3.7,0
  Top Layer region: 0,38.9 0,35.55 0.8,35.55 0.8,38.1 3.701,38.1 3.701,38.9
  body extent 0.4,0.4 51.2,38.5, height 5.08
SKY13431-374LF [mm] "6 Pin DFN"
  rrect50% 0.35x0.25 smd mask+0.05: 1(-0.725,0.5) 2(-0.725,0) 3(-0.725,-0.5) 4(0.725,-0.5) 5(0.725,0) 6(0.725,0.5)
  rrect30% 0.7x1.2 smd mask+0.05: 7(0,0)
  silkscreen extent -0.92,0.8 -0.83,0.9, body extent -0.75,-0.75 0.75,0.75, height 0.5
SO-8 [mm] "SOP, 8-Leads, Body 4,90x3,90mm, Pitch 1,27mm, IPC Medium Density"
  oval 1.45x0.6 smd: 1(-2.725,1.905) 2(-2.725,0.635) 3(-2.725,-0.635) 4(-2.725,-1.905) 5(2.725,-1.905) 6(2.725,-0.635) 7(2.725,0.635) 8(2.725,1.905)
  silkscreen extent -2.85,-2.5 1.6,2.88, body extent -3,-2.45 3,2.45, height 1.7
SOD-232 [mm] "Testpoint"
  rect 0.9x0.5 smd: 1(-1.125,0) 2(1.125,0)
  silkscreen extent -0.9,-0.75 1.4,0.75, body extent -0.9,-0.72 0.9,0.72, height 1.17
SPBT3.0DP2 [mm] "Bluetooth v3.0, SPP and HID profiles, Class 2 module, 128-bit encryption security, ? ST Cortex-M4 microprocessor, 512 KB Flash, 128 KB RAM"
  rect 1.2x1.3 smd: 1(0,0) 2(1.5,0) 3(3,0) 4(4.5,0) 5(6,0) 6(7.5,0) 7(9,0) 8(9,13.2) 9(7.5,13.2) 10(6,13.2) 11(4.5,13.208) 12(3,13.2) 13(1.5,13.2) 14(0,13.2)
  rect 1.3x1.2 smd: 15(-1.15,5.85) 16(-1.15,4.45) 17(-1.15,3.05) 18(-1.15,1.65)
  rect 1x0.8 smd: 19(-0.7,11.915) 20(-0.7,10.95) 21(-0.7,9.985) 22(-0.7,9.02) 23(-0.7,8.055) 24(-0.7,7.09)
  silkscreen extent -1.44,-0.13 10.41,13.63, body extent -1.31,0 10.29,13.5, height 1.3
ST25RU3993_QFN48_0.5mm_pitch [mm] "QFN, 48-Leads, Body 7,0x7,0mm (max), Pitch 0,50mm, IPC Medium Density"
  rect 0.55x0.3 smd paste+0 mask+0.05: 1(-3.35,2.75) 12(-3.35,-2.75) 25(3.35,-2.75) 36(3.35,2.75)
  rect 0.75x0.3 smd mask+0.05: 2(-3.25,2.25)
  rect 0.75x0.3 smd paste+0 mask+0.05: 3(-3.25,1.75) 4(-3.25,1.25) 5(-3.25,0.75) 6(-3.25,0.25) 7(-3.25,-0.25) 8(-3.25,-0.75) 9(-3.25,-1.25) 10(-3.25,-1.75) 11(-3.25,-2.25) 26(3.25,-2.25) 27(3.25,-1.75) 28(3.25,-1.25) 29(3.25,-0.75) 30(3.25,-0.25) 31(3.25,0.25) 32(3.25,0.75) 33(3.25,1.25) 34(3.25,1.75) 35(3.25,2.25)
  rect 0.3x0.55 smd paste+0 mask+0.05: 13(-2.75,-3.35) 24(2.75,-3.35) 37(2.75,3.35) 48(-2.75,3.35)
  rect 0.3x0.75 smd paste+0 mask+0.05: 14(-2.25,-3.25) 15(-1.75,-3.25) 16(-1.25,-3.25) 17(-0.75,-3.25) 18(-0.25,-3.25) 19(0.25,-3.25) 20(0.75,-3.25) 21(1.25,-3.25) 22(1.75,-3.25) 23(2.25,-3.25) 38(2.25,3.25) 39(1.75,3.25) 40(1.25,3.25) 41(0.75,3.25) 42(0.25,3.25) 43(-0.25,3.25) 44(-0.75,3.25) 45(-1.25,3.25) 46(-1.75,3.25) 47(-2.25,3.25)
  rect 5.24x5.24 smd mask+0.07: 49(0,0)
  silkscreen extent -3.8,-3.8 3.8,4.15, body extent -3.5,-3.5 3.5,3.5, height 1
SW_SPST_KMR211G [mm]
  rect 0.9x1 smd paste+0 mask+0: 1(-2.025,0.825) 2(-2.025,-0.775) 3(2.075,-0.775) 4(2.075,0.825)
  silkscreen extent -2.19,-1.49 2.23,1.56, body extent -2.28,-1.36 2.32,1.44, height 1.9
TC2050-IDC-FP [mil] "TC2050-IDC  10-Pin Plug-of-NailsTM"
  round 31 smd: 1(50,-25) 2(100,-25) 3(150,-25) 4(200,-25) 5(250,-25) 6(250,25) 7(200,25) 8(150,25) 9(100,25) 10(50,25)
  round 34 hole 39 unplated: A(0,0) B(300,39.96) C(300,-39.96)
  round 0 hole 93.46 unplated paste+0: ""(0,100) ""(0,-100) ""(225,100) ""(225,-100)
  silkscreen extent -61,-161 330,161
TP#1 [mm] "Testpoint"
  round 1 smd paste+0 mask+0: 1(0,0)
TP#2 [mm] "Testpoint"
  round 1 smd paste+0 mask+0: 1(0.485,28.755)
TQP9107 [mm] "699 – 960 MHz 2-stage Power Amplifier"
  rect 0.27x0.62 smd mask+0.05: 1(2,1.62) 2(1.5,1.62) 4(0,1.62) 6(-2,1.62) 7(-2,-1.62) 9(0,-1.62) 10(0.5,-1.62) 11(1,-1.62) 12(1.5,-1.62) 13(2,-1.62)
  rect 0.77x0.62 smd mask+0.05: 3(0.75,1.62)
  rect 1.27x0.62 smd mask+0.05: 5(-1,1.62) 8(-1,-1.62)
  rect 4.28x2.16 smd mask+0.05: 14(0,0)
  silkscreen extent -2.53,-2.03 2.53,2.55, body extent -2.25,-1.75 2.25,1.75, height 0.85
"µUSB Molex" [mm] "105017"
  rect 0.4x1.35 smd: 1(-1.3,0) 2(-0.65,0) 3(0,0) 4(0.65,0) 5(1.3,0)
  oval 0.6x1.3 hole 0.6 slot 1.3 at 90 deg: 6(-3.5,-2.7) 6(3.5,-2.7)
  rrect40% 1.6x1.9 smd: 6(-3.301,-2.7) 6(3.301,-2.7)
  rect 1.5x1.9 smd: 6(-3,-2.7) 6(-1,-2.7) 6(1,-2.7) 6(3,-2.7)
  round 1.45 hole 0.85: ""(-2.5,0) ""(2.5,0)
  Top Layer region: -2.235,-3.658 -3.785,-3.658 -3.85,-3.658 -3.972,-3.607 -4.065,-3.514 -4.115,-3.393 -4.115,-3.327 -4.115,-3.327 -4.115,-2.083 -4.115,-2.017 -4.065,-1.896 -3.972,-1.803 -3.85,-1.753 -3.785,-1.753 -3.785,-1.753 -2.235,-1.753
  silkscreen extent -4.5,-3.5 4.5,1.5, body extent -4.1,-5.15 4.1,0.25, height 2.78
